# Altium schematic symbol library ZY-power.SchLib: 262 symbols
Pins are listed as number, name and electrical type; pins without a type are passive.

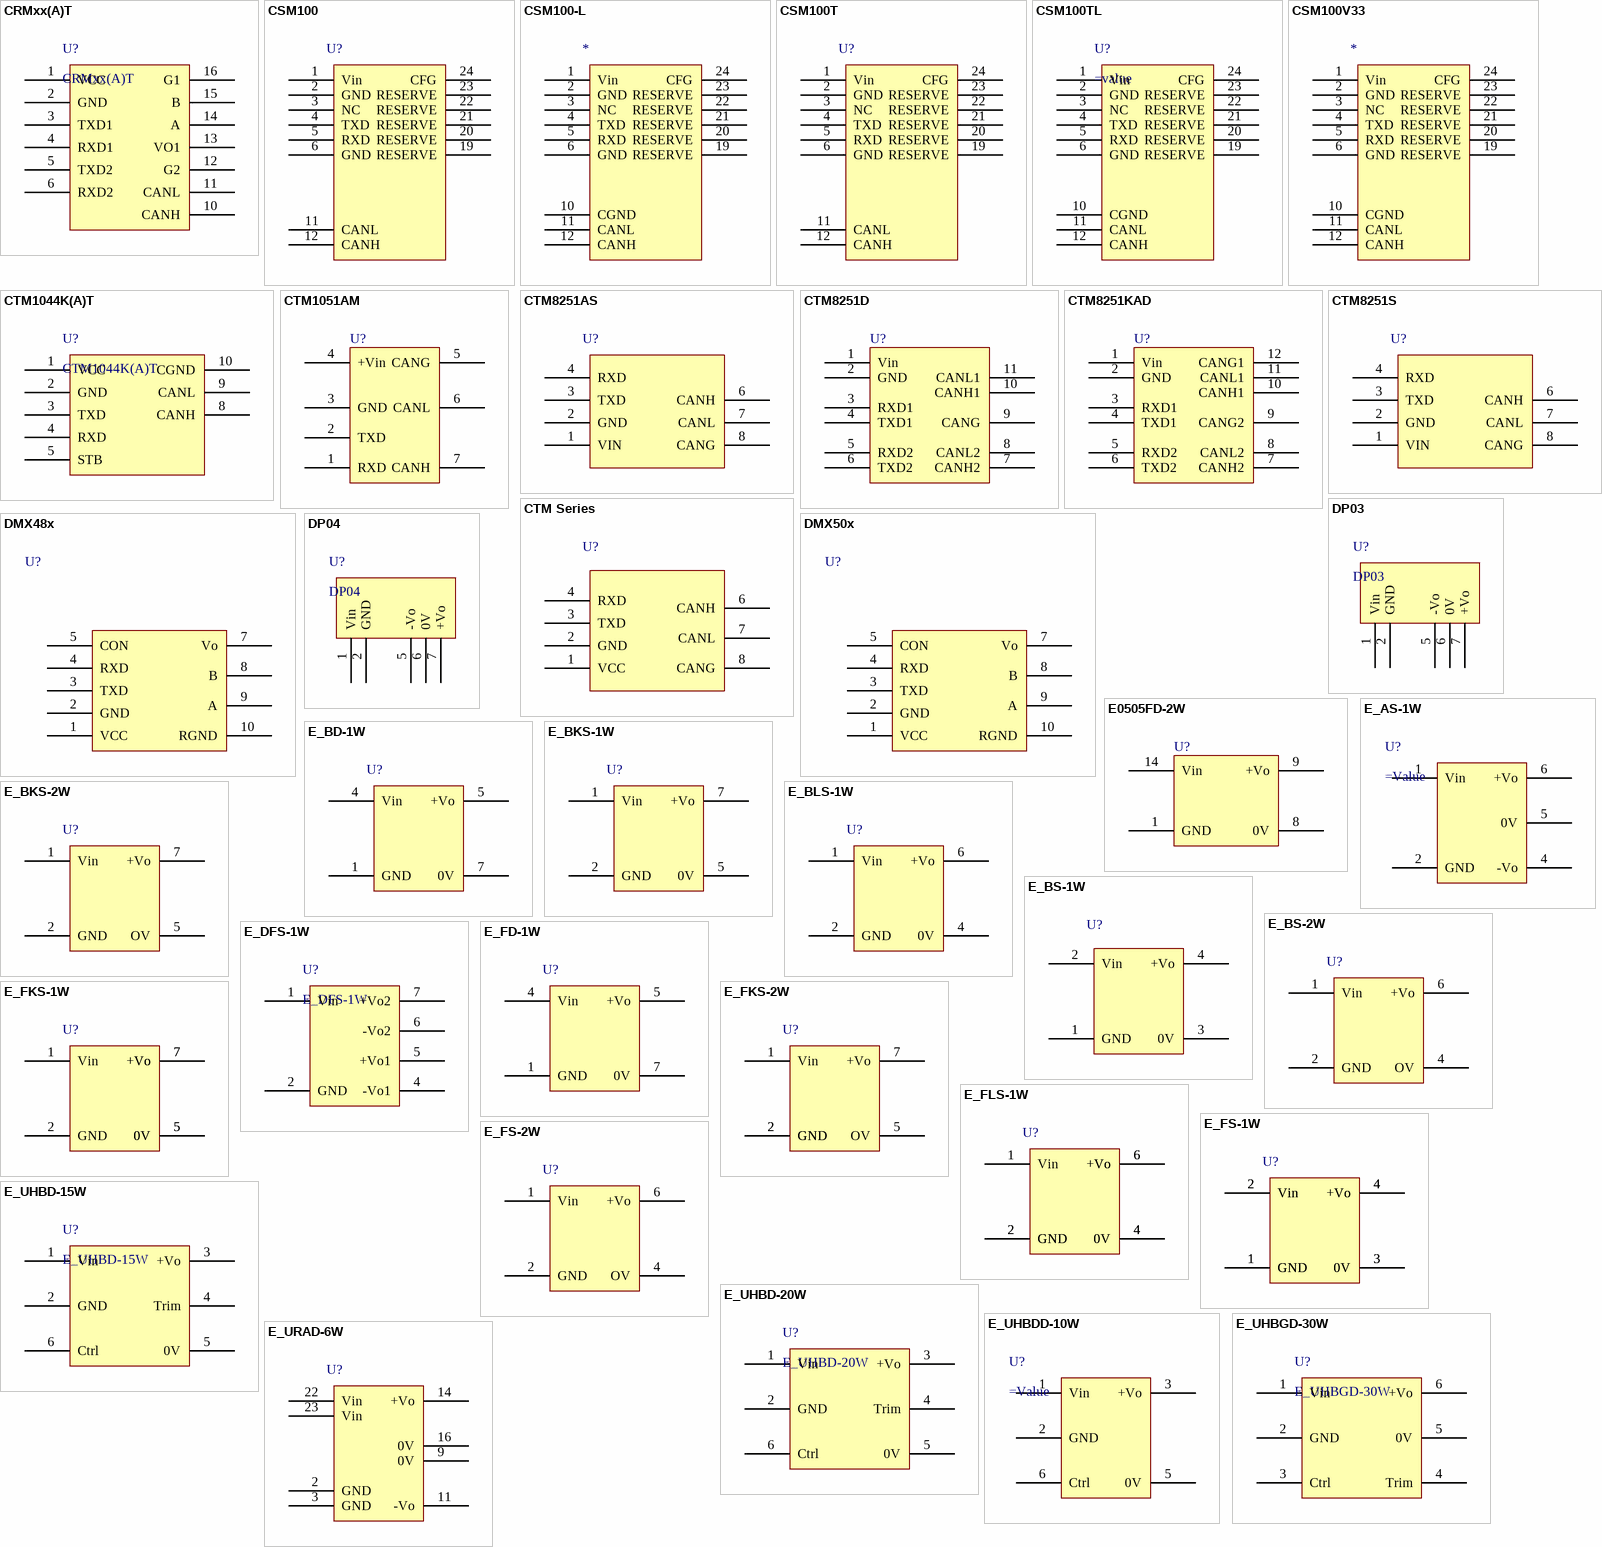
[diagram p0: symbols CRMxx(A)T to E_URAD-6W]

## CRMxx(A)T
designator U?
footprint CRMxx(A)T
pins: 1 VCC, 2 GND, 3 TXD1, 4 RXD1, 5 TXD2, 6 RXD2, 10 CANH, 11 CANL, 12 G2, 13 VO1, 14 A, 15 B, 16 G1

## CSM100
designator U?
footprint CSM100 (嵌入式CAN-bus接口芯片)
pins: 1 Vin, 2 GND, 3 NC, 4 TXD, 5 RXD, 6 GND, 11 CANL, 12 CANH, 19 RESERVE, 20 RESERVE, 21 RESERVE, 22 RESERVE, 23 RESERVE, 24 CFG

## CSM100-L
designator *
footprint CSM100-L
pins: 1 Vin, 2 GND, 3 NC, 4 TXD, 5 RXD, 6 GND, 10 CGND, 11 CANL, 12 CANH, 19 RESERVE, 20 RESERVE, 21 RESERVE, 22 RESERVE, 23 RESERVE, 24 CFG

## CSM100T
designator U?
footprint CSM100T (Footprint not found)
pins: 1 Vin, 2 GND, 3 NC, 4 TXD, 5 RXD, 6 GND, 11 CANL, 12 CANH, 19 RESERVE, 20 RESERVE, 21 RESERVE, 22 RESERVE, 23 RESERVE, 24 CFG

## CSM100TL
designator U?
CSM100TL
footprint CSM100TL
pins: 1 Vin, 2 GND, 3 NC, 4 TXD, 5 RXD, 6 GND, 10 CGND, 11 CANL, 12 CANH, 19 RESERVE, 20 RESERVE, 21 RESERVE, 22 RESERVE, 23 RESERVE, 24 CFG

## CSM100V33
designator *
footprint CSM100V33 (Footprint not found)
pins: 1 Vin, 2 GND, 3 NC, 4 TXD, 5 RXD, 6 GND, 10 CGND, 11 CANL, 12 CANH, 19 RESERVE, 20 RESERVE, 21 RESERVE, 22 RESERVE, 23 RESERVE, 24 CFG

## CTM1044K(A)T
designator U?
footprint CTM1044K(A)T
pins: 1 VCC, 2 GND, 3 TXD, 4 RXD, 5 STB, 8 CANH, 9 CANL, 10 CGND

## CTM1051AM
designator U?
pins: 1 RXD, 2 TXD, 3 GND, 4 +Vin, 5 CANG, 6 CANL, 7 CANH

## CTM8251AS
designator U?
CTM8251AS
footprint CTM8251AS
pins: 1 VIN, 2 GND, 3 TXD, 4 RXD, 6 CANH, 7 CANL, 8 CANG

## CTM8251D
designator U?
footprint CTM8251D
pins: 1 Vin, 2 GND, 3 RXD1, 4 TXD1, 5 RXD2, 6 TXD2, 7 CANH2, 8 CANL2, 9 CANG, 10 CANH1, 11 CANL1

## CTM8251KAD
designator U?
pins: 1 Vin, 2 GND, 3 RXD1, 4 TXD1, 5 RXD2, 6 TXD2, 7 CANH2, 8 CANL2, 9 CANG2, 10 CANH1, 11 CANL1, 12 CANG1

## CTM8251S
designator U?
CTM8251S
footprint CTM8251S
pins: 1 VIN, 2 GND, 3 TXD, 4 RXD, 6 CANH, 7 CANL, 8 CANG

## CTM Series
designator U?
footprint CTM Series (Footprint not found)
pins: 1 VCC, 2 GND, 3 TXD, 4 RXD, 6 CANH, 7 CANL, 8 CANG

## DMX48x
designator U?
footprint DMX48x
pins: 1 VCC, 2 GND, 3 TXD, 4 RXD, 5 CON, 7 Vo, 8 B, 9 A, 10 RGND
2 alternate drawings of the same symbol

## DMX50x
designator U?
footprint DMX50x
pins: 1 VCC, 2 GND, 3 TXD, 4 RXD, 5 CON, 7 Vo, 8 B, 9 A, 10 RGND
2 alternate drawings of the same symbol

## DP03
designator U?
footprint DP03
pins: 1 Vin, 2 GND, 5 -Vo, 6 0V, 7 +Vo

## DP04
designator U?
footprint DP04
pins: 1 Vin, 2 GND, 5 -Vo, 6 0V, 7 +Vo

## E0505FD-2W
designator U?
pins: 1 GND, 8 0V, 9 +Vo, 14 Vin

## E_AS-1W
designator U?
footprint E_AS-1W
pins: 1 Vin, 2 GND, 4 -Vo, 5 0V, 6 +Vo

## E_BD-1W
designator U?
footprint E_BD-1W
pins: 1 GND, 4 Vin, 5 +Vo, 7 0V

## E_BKS-1W
designator U?
footprint E_BKS-1W
pins: 1 Vin, 2 GND, 5 0V, 7 +Vo

## E_BKS-2W
designator U?
footprint E_BKS-2W
pins: 1 Vin, 2 GND, 5 OV, 7 +Vo

## E_BLS-1W
designator U?
footprint E_BLS-1W
pins: 1 Vin, 2 GND, 4 0V, 6 +Vo

## E_BS-1W
designator U?
footprint E_BS-1W
pins: 1 GND, 2 Vin, 3 0V, 4 +Vo

## E_BS-2W
designator U?
footprint E_BS-2W
pins: 1 Vin, 2 GND, 4 OV, 6 +Vo

## E_DFS-1W
designator U?
footprint E_DFS-1W
pins: 1 Vin, 2 GND, 4 -Vo1, 5 +Vo1, 6 -Vo2, 7 +Vo2

## E_FD-1W
designator U?
footprint E_FD-1W
pins: 1 GND, 4 Vin, 5 +Vo, 7 0V

## E_FKS-1W
designator U?
footprint E_FKS-1W
pins: 1 Vin, 2 GND, 5 0V, 5 0V, 7 +Vo, 7 +Vo

## E_FKS-2W
designator U?
footprint E_FKS-2W
pins: 1 Vin, 2 GND, 2 GND, 5 OV, 7 +Vo

## E_FLS-1W
designator U?
footprint E_FLS-1W
pins: 1 Vin, 2 GND, 2 GND, 4 0V, 4 0V, 6 +Vo, 6 +Vo

## E_FS-1W
designator U?
pins: 1 GND, 1 GND, 2 Vin, 2 Vin, 3 0V, 3 0V, 4 +Vo, 4 +Vo

## E_FS-2W
designator U?
footprint E_FS-2W
pins: 1 Vin, 2 GND, 4 OV, 6 +Vo

## E_UHBD-15W
designator U?
footprint E_UHBD-15W
pins: 1 Vin, 2 GND, 3 +Vo, 4 Trim, 5 0V, 6 Ctrl

## E_UHBD-20W
designator U?
footprint E_UHBD-20W
pins: 1 Vin, 2 GND, 3 +Vo, 4 Trim, 5 0V, 6 Ctrl

## E_UHBDD-10W
designator U?
footprint E_UHBDD-10W
pins: 1 Vin, 2 GND, 3 +Vo, 5 0V, 6 Ctrl

## E_UHBGD-30W
designator U?
footprint E_UHBGD-30W
pins: 1 Vin, 2 GND, 3 Ctrl, 4 Trim, 5 0V, 6 +Vo

## E_URAD-6W
designator U?
footprint E_URAD-6W
pins: 2 GND, 3 GND, 9 0V, 11 -Vo, 14 +Vo, 16 0V, 22 Vin, 23 Vin

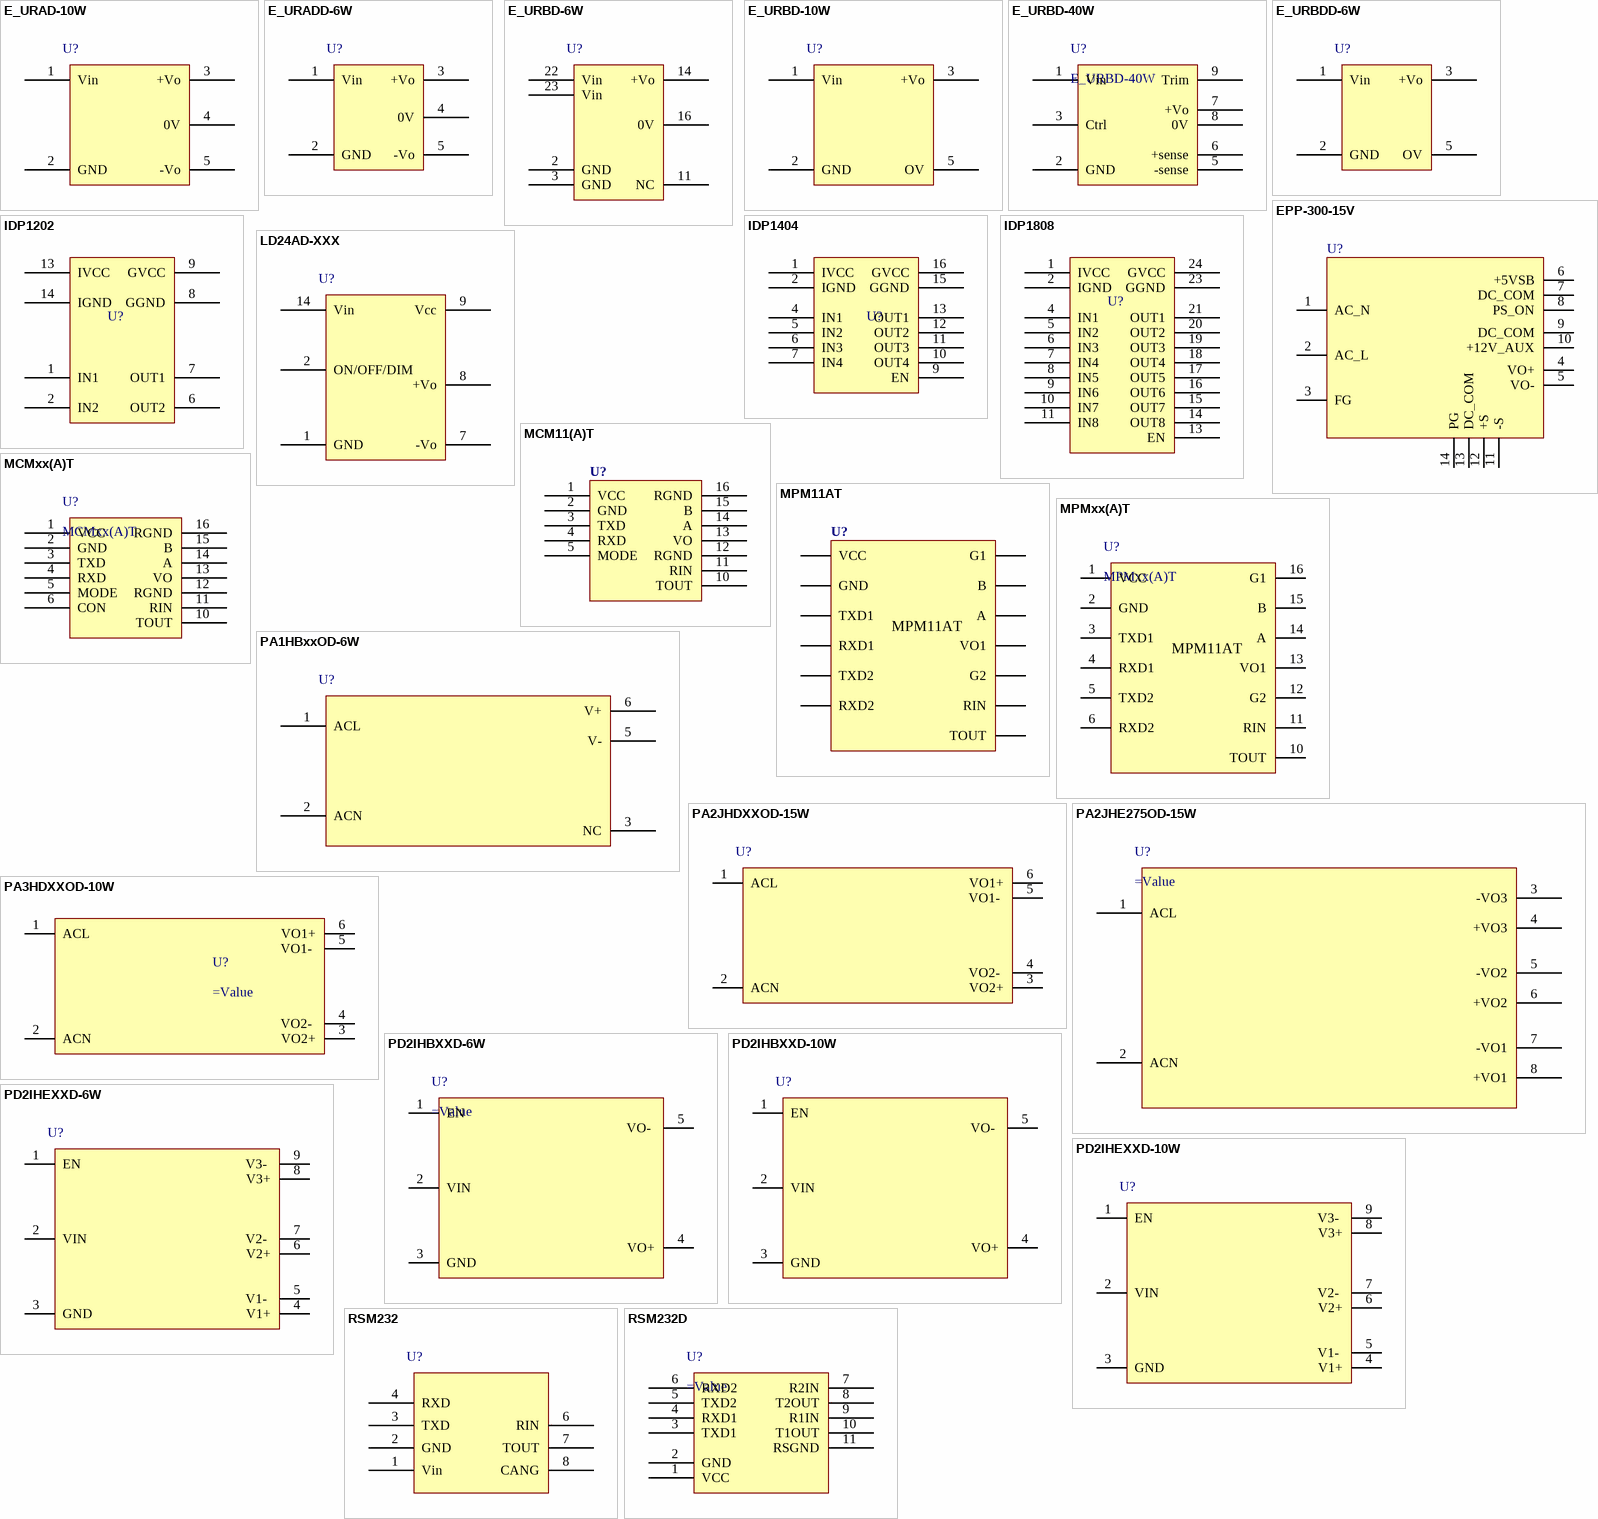
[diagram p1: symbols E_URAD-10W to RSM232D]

## E_URAD-10W
designator U?
footprint E_URAD-10W
pins: 1 Vin, 2 GND, 3 +Vo, 4 0V, 5 -Vo

## E_URADD-6W
designator U?
footprint E_URADD-6W
pins: 1 Vin, 2 GND, 3 +Vo, 4 0V, 5 -Vo

## E_URBD-6W
designator U?
footprint E_URBD-6W
pins: 2 GND, 3 GND, 11 NC, 14 +Vo, 16 0V, 22 Vin, 23 Vin

## E_URBD-10W
designator U?
footprint E_URBD-10W
pins: 1 Vin, 2 GND, 3 +Vo, 5 OV

## E_URBD-40W
designator U?
footprint E_URBD-40W
pins: 1 Vin, 2 GND, 3 Ctrl, 5 -sense, 6 +sense, 7 +Vo, 8 0V, 9 Trim

## E_URBDD-6W
designator U?
footprint E_URBDD-6W
pins: 1 Vin, 2 GND, 3 +Vo, 5 OV

## EPP-300-15V
designator U?
pins: 1 AC_N, 2 AC_L, 3 FG, 4 VO+, 5 VO-, 6 +5VSB, 7 DC_COM, 8 PS_ON, 9 DC_COM, 10 +12V_AUX, 11 -S, 12 +S, 13 DC_COM, 14 PG

## IDP1202
designator U?
footprint IDP1202 (20x10x8mm)
pins: 1 IN1, 2 IN2, 6 OUT2, 7 OUT1, 8 GGND, 9 GVCC, 13 IVCC, 14 IGND

## IDP1404
designator U?
footprint IDP1404
pins: 1 IVCC, 2 IGND, 4 IN1, 5 IN2, 6 IN3, 7 IN4, 9 EN, 10 OUT4, 11 OUT3, 12 OUT2, 13 OUT1, 15 GGND, 16 GVCC

## IDP1808
designator U?
footprint IDP1808 (32.32x14.41x6.7(9.65)mm)
pins: 1 IVCC, 2 IGND, 4 IN1, 5 IN2, 6 IN3, 7 IN4, 8 IN5, 9 IN6, 10 IN7, 11 IN8, 13 EN, 14 OUT8, 15 OUT7, 16 OUT6, 17 OUT5, 18 OUT4, 19 OUT3, 20 OUT2, 21 OUT1, 23 GGND, 24 GVCC

## LD24AD-XXX
designator U?
footprint LD24AD-XXX
pins: 1 GND, 2 ON/OFF/DIM, 7 -Vo, 8 +Vo, 9 Vcc, 14 Vin

## MCM11(A)T
designator U?
pins: 1 VCC, 2 GND, 3 TXD, 4 RXD, 5 MODE, 10 TOUT, 11 RIN, 12 RGND, 13 VO, 14 A, 15 B, 16 RGND

## MCMxx(A)T
designator U?
footprint MCMxx(A)T
pins: 1 VCC, 2 GND, 3 TXD, 4 RXD, 5 MODE, 6 CON, 10 TOUT, 11 RIN, 12 RGND, 13 VO, 14 A, 15 B, 16 RGND

## MPM11AT
designator U?
pins: 1 VCC, 2 GND, 3 TXD1, 4 RXD1, 5 TXD2, 6 RXD2, 10 TOUT, 11 RIN, 12 G2, 13 VO1, 14 A, 15 B, 16 G1

## MPMxx(A)T
designator U?
footprint MPMxx(A)T
pins: 1 VCC, 2 GND, 3 TXD1, 4 RXD1, 5 TXD2, 6 RXD2, 10 TOUT, 11 RIN, 12 G2, 13 VO1, 14 A, 15 B, 16 G1

## PA1HBxxOD-6W
designator U?
footprint PA1HBxxOD-6W
pins: 1 ACL, 2 ACN, 3 NC, 5 V-, 6 V+

## PA2JHDXXOD-15W
designator U?
footprint PA2JHDXXOD-15W
pins: 1 ACL, 2 ACN, 3 VO2+, 4 VO2- , 5 VO1- , 6 VO1+

## PA2JHE275OD-15W
designator U?
footprint PA2JHE275OD-15W
pins: 1 ACL, 2 ACN, 3 -VO3, 4 +VO3, 5 -VO2, 6 +VO2, 7 -VO1, 8 +VO1

## PA3HDXXOD-10W
designator U?
footprint PA3HDXXOD-10W
pins: 1 ACL, 2 ACN, 3 VO2+, 4 VO2- , 5 VO1- , 6 VO1+

## PD2IHBXXD-6W
designator U?
footprint PD2IHBXXD-6W
pins: 1 EN, 2 VIN, 3 GND, 4 VO+, 5 VO- 

## PD2IHBXXD-10W
designator U?
footprint PD2IHBXXD-10W
pins: 1 EN, 2 VIN, 3 GND, 4 VO+, 5 VO- 

## PD2IHEXXD-6W
designator U?
footprint PD2IHEXXD-6W
pins: 1 EN, 2 VIN, 3 GND, 4 V1+, 5 V1- , 6 V2+, 7 V2- , 8 V3+, 9 V3- 

## PD2IHEXXD-10W
designator U?
footprint PD2IHEXXD-10W
pins: 1 EN, 2 VIN, 3 GND, 4 V1+, 5 V1- , 6 V2+, 7 V2- , 8 V3+, 9 V3- 

## RSM232
designator U?
footprint RSM232 (Footprint not found)
pins: 1 Vin, 2 GND, 3 TXD, 4 RXD, 6 RIN, 7 TOUT, 8 CANG

## RSM232D
designator U?
footprint RSM232D
pins: 1 VCC, 2 GND, 3 TXD1, 4 RXD1, 5 TXD2, 6 RXD2, 7 R2IN, 8 T2OUT, 9 R1IN, 10 T1OUT, 11 RSGND

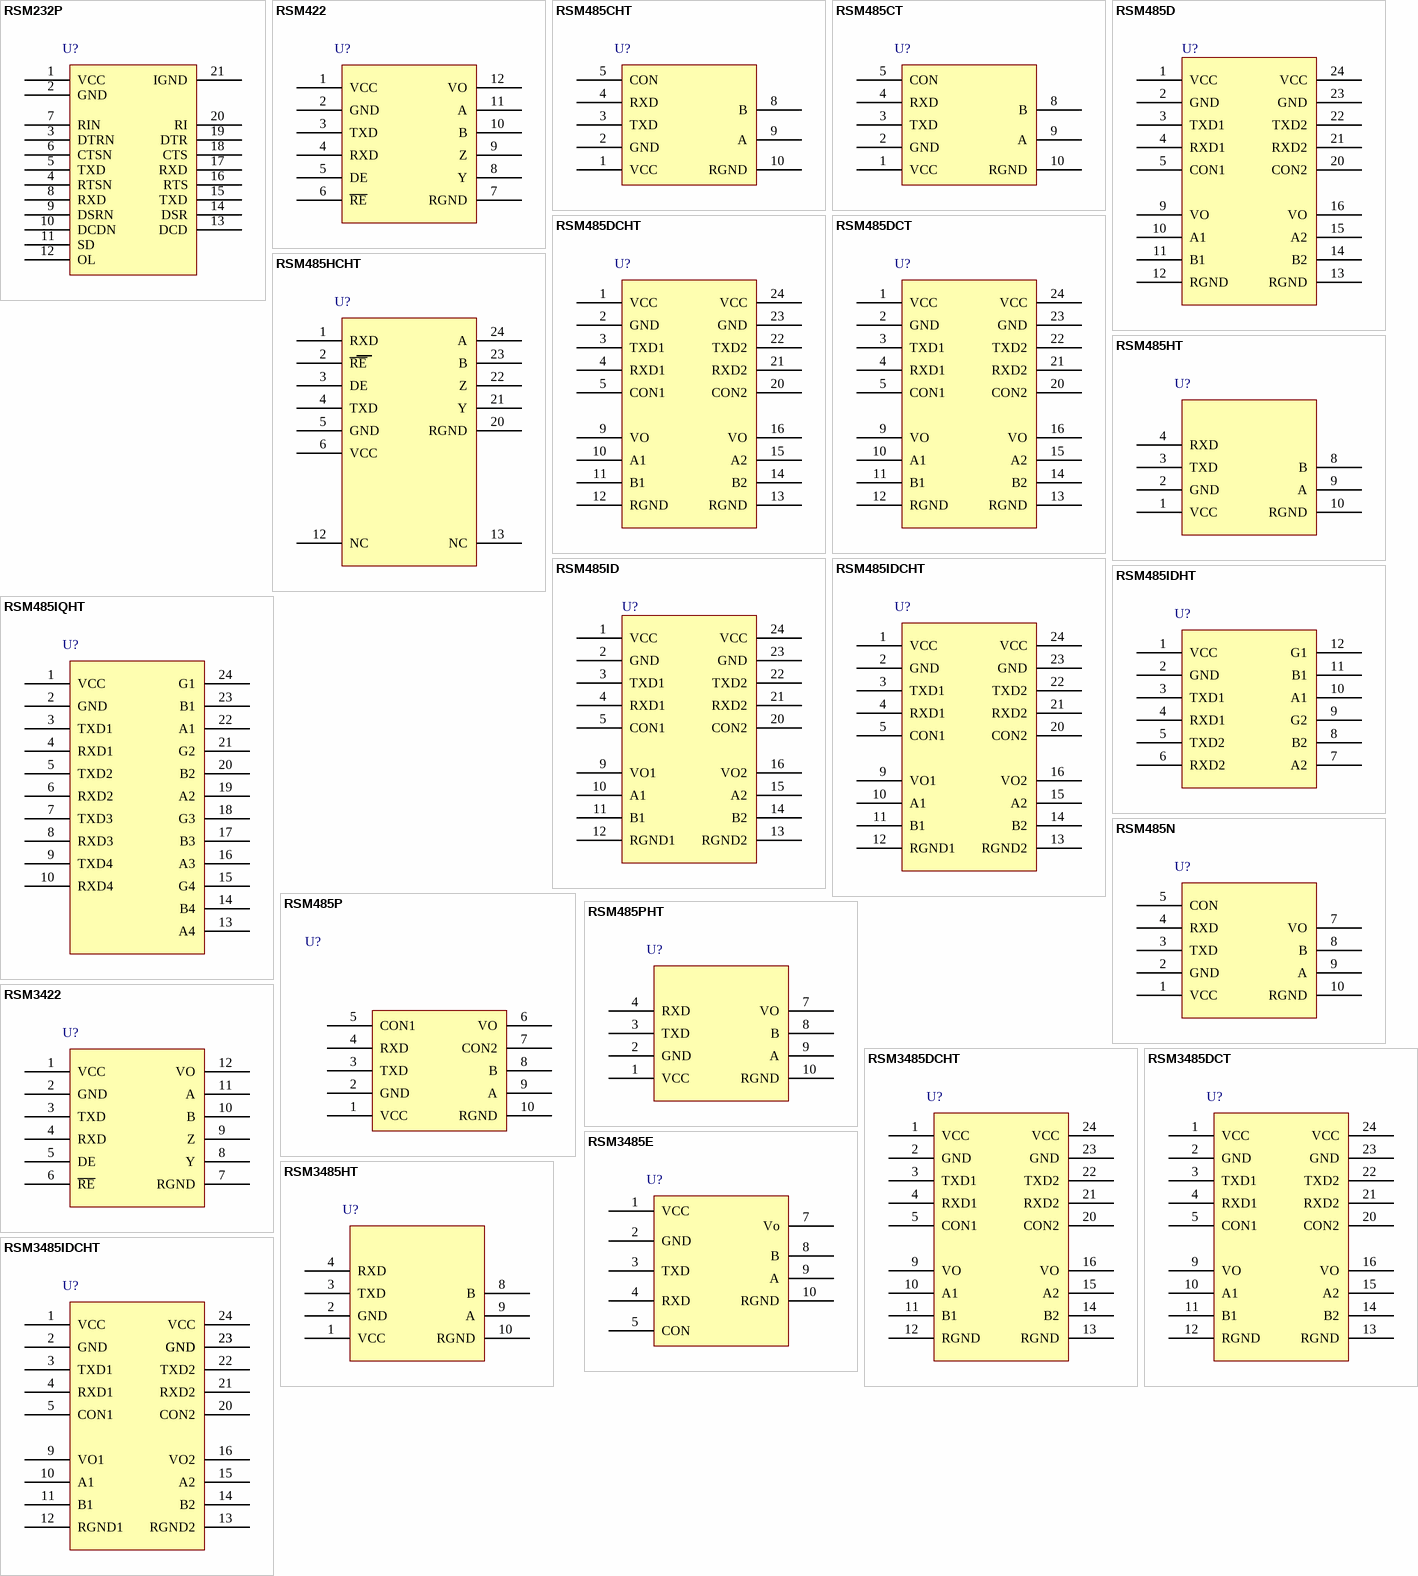
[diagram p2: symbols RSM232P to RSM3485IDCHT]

## RSM232P
designator U?
footprint RSM232P (Footprint not found)
pins: 1 VCC, 2 GND, 3 DTRN, 4 RTSN, 5 TXD, 6 CTSN, 7 RIN, 8 RXD, 9 DSRN, 10 DCDN, 11 SD, 12 OL, 13 DCD, 14 DSR, 15 TXD, 16 RTS, 17 RXD, 18 CTS, 19 DTR, 20 RI, 21 IGND

## RSM422
designator U?
RSM422
footprint RSM422
pins: 1 VCC, 2 GND, 3 TXD, 4 RXD, 5 DE, 6 ~{RE}, 7 RGND, 8 Y, 9 Z, 10 B, 11 A, 12 VO

## RSM485CHT
designator U?
footprint RSM485CHT (Footprint not found)
pins: 1 VCC, 2 GND, 3 TXD, 4 RXD, 5 CON, 8 B, 9 A, 10 RGND

## RSM485CT
designator U?
footprint RSM485CT (Footprint not found)
pins: 1 VCC, 2 GND, 3 TXD, 4 RXD, 5 CON, 8 B, 9 A, 10 RGND

## RSM485D
designator U?
footprint RSM485D
pins: 1 VCC, 2 GND, 3 TXD1, 4 RXD1, 5 CON1, 9 VO, 10 A1, 11 B1, 12 RGND, 13 RGND, 14 B2, 15 A2, 16 VO, 20 CON2, 21 RXD2, 22 TXD2, 23 GND, 24 VCC
2 alternate drawings of the same symbol

## RSM485DCHT
designator U?
RSM485DCHT
footprint RSM485DCHT
pins: 1 VCC, 2 GND, 3 TXD1, 4 RXD1, 5 CON1, 9 VO, 10 A1, 11 B1, 12 RGND, 13 RGND, 14 B2, 15 A2, 16 VO, 20 CON2, 21 RXD2, 22 TXD2, 23 GND, 24 VCC

## RSM485DCT
designator U?
RSM485DCT
footprint RSM485DCT
pins: 1 VCC, 2 GND, 3 TXD1, 4 RXD1, 5 CON1, 9 VO, 10 A1, 11 B1, 12 RGND, 13 RGND, 14 B2, 15 A2, 16 VO, 20 CON2, 21 RXD2, 22 TXD2, 23 GND, 24 VCC

## RSM485HCHT
designator U?
RSM485HCHT
footprint RSM485HCHT
pins: 1 RXD, 2 ~{RE}, 3 DE, 4 TXD, 5 GND, 6 VCC, 12 NC, 13 NC, 20 RGND, 21 Y, 22 Z, 23 B, 24 A

## RSM485HT
designator U?
RSM485HT
footprint RSM485HT
pins: 1 VCC, 2 GND, 3 TXD, 4 RXD, 8 B, 9 A, 10 RGND

## RSM485ID
designator U?
footprint RSM485D
pins: 1 VCC, 2 GND, 3 TXD1, 4 RXD1, 5 CON1, 9 VO1, 10 A1, 11 B1, 12 RGND1, 13 RGND2, 14 B2, 15 A2, 16 VO2, 20 CON2, 21 RXD2, 22 TXD2, 23 GND, 24 VCC
2 alternate drawings of the same symbol

## RSM485IDCHT
designator U?
RSM485IDCHT
footprint RSM485IDCHT
pins: 1 VCC, 2 GND, 3 TXD1, 4 RXD1, 5 CON1, 9 VO1, 10 A1, 11 B1, 12 RGND1, 13 RGND2, 14 B2, 15 A2, 16 VO2, 20 CON2, 21 RXD2, 22 TXD2, 23 GND, 24 VCC

## RSM485IDHT
designator U?
RSM485IDHT
footprint RSM485IDHT
pins: 1 VCC, 2 GND, 3 TXD1, 4 RXD1, 5 TXD2, 6 RXD2, 7 A2, 8 B2, 9 G2, 10 A1, 11 B1, 12 G1

## RSM485IQHT
designator U?
RSM485IQHT
footprint RSM485IQHT
pins: 1 VCC, 2 GND, 3 TXD1, 4 RXD1, 5 TXD2, 6 RXD2, 7 TXD3, 8 RXD3, 9 TXD4, 10 RXD4, 13 A4, 14 B4, 15 G4, 16 A3, 17 B3, 18 G3, 19 A2, 20 B2, 21 G2, 22 A1, 23 B1, 24 G1

## RSM485N
designator U?
RSM485N
footprint RSM485N
pins: 1 VCC, 2 GND, 3 TXD, 4 RXD, 5 CON, 7 VO, 8 B, 9 A, 10 RGND

## RSM485P
designator U?
RSM485P
footprint RSM485P
pins: 1 VCC, 2 GND, 3 TXD, 4 RXD, 5 CON1, 6 VO, 7 CON2, 8 B, 9 A, 10 RGND
2 alternate drawings of the same symbol

## RSM485PHT
designator U?
RSM485PHT
footprint RSM485PHT
pins: 1 VCC, 2 GND, 3 TXD, 4 RXD, 7 VO, 8 B, 9 A, 10 RGND

## RSM3422
designator U?
RSM3422
footprint RSM3422
pins: 1 VCC, 2 GND, 3 TXD, 4 RXD, 5 DE, 6 ~{RE}, 7 RGND, 8 Y, 9 Z, 10 B, 11 A, 12 VO

## RSM3485DCHT
designator U?
RSM3485DCHT
footprint RSM3485DCHT
pins: 1 VCC, 2 GND, 3 TXD1, 4 RXD1, 5 CON1, 9 VO, 10 A1, 11 B1, 12 RGND, 13 RGND, 14 B2, 15 A2, 16 VO, 20 CON2, 21 RXD2, 22 TXD2, 23 GND, 24 VCC

## RSM3485DCT
designator U?
RSM3485DCT
footprint RSM3485DCT
pins: 1 VCC, 2 GND, 3 TXD1, 4 RXD1, 5 CON1, 9 VO, 10 A1, 11 B1, 12 RGND, 13 RGND, 14 B2, 15 A2, 16 VO, 20 CON2, 21 RXD2, 22 TXD2, 23 GND, 24 VCC

## RSM3485E
designator U?
pins: 1 VCC, 2 GND, 3 TXD, 4 RXD, 5 CON, 7 Vo, 8 B, 9 A, 10 RGND

## RSM3485HT
designator U?
RSM3485HT
footprint RSM3485HT
pins: 1 VCC, 2 GND, 3 TXD, 4 RXD, 8 B, 9 A, 10 RGND

## RSM3485IDCHT
designator U?
RSM3485IDCHT
footprint RSM3485IDCHT
pins: 1 VCC, 2 GND, 3 TXD1, 4 RXD1, 5 CON1, 9 VO1, 10 A1, 11 B1, 12 RGND1, 13 RGND2, 14 B2, 15 A2, 16 VO2, 20 CON2, 21 RXD2, 22 TXD2, 23 GND, 23 GND, 24 VCC

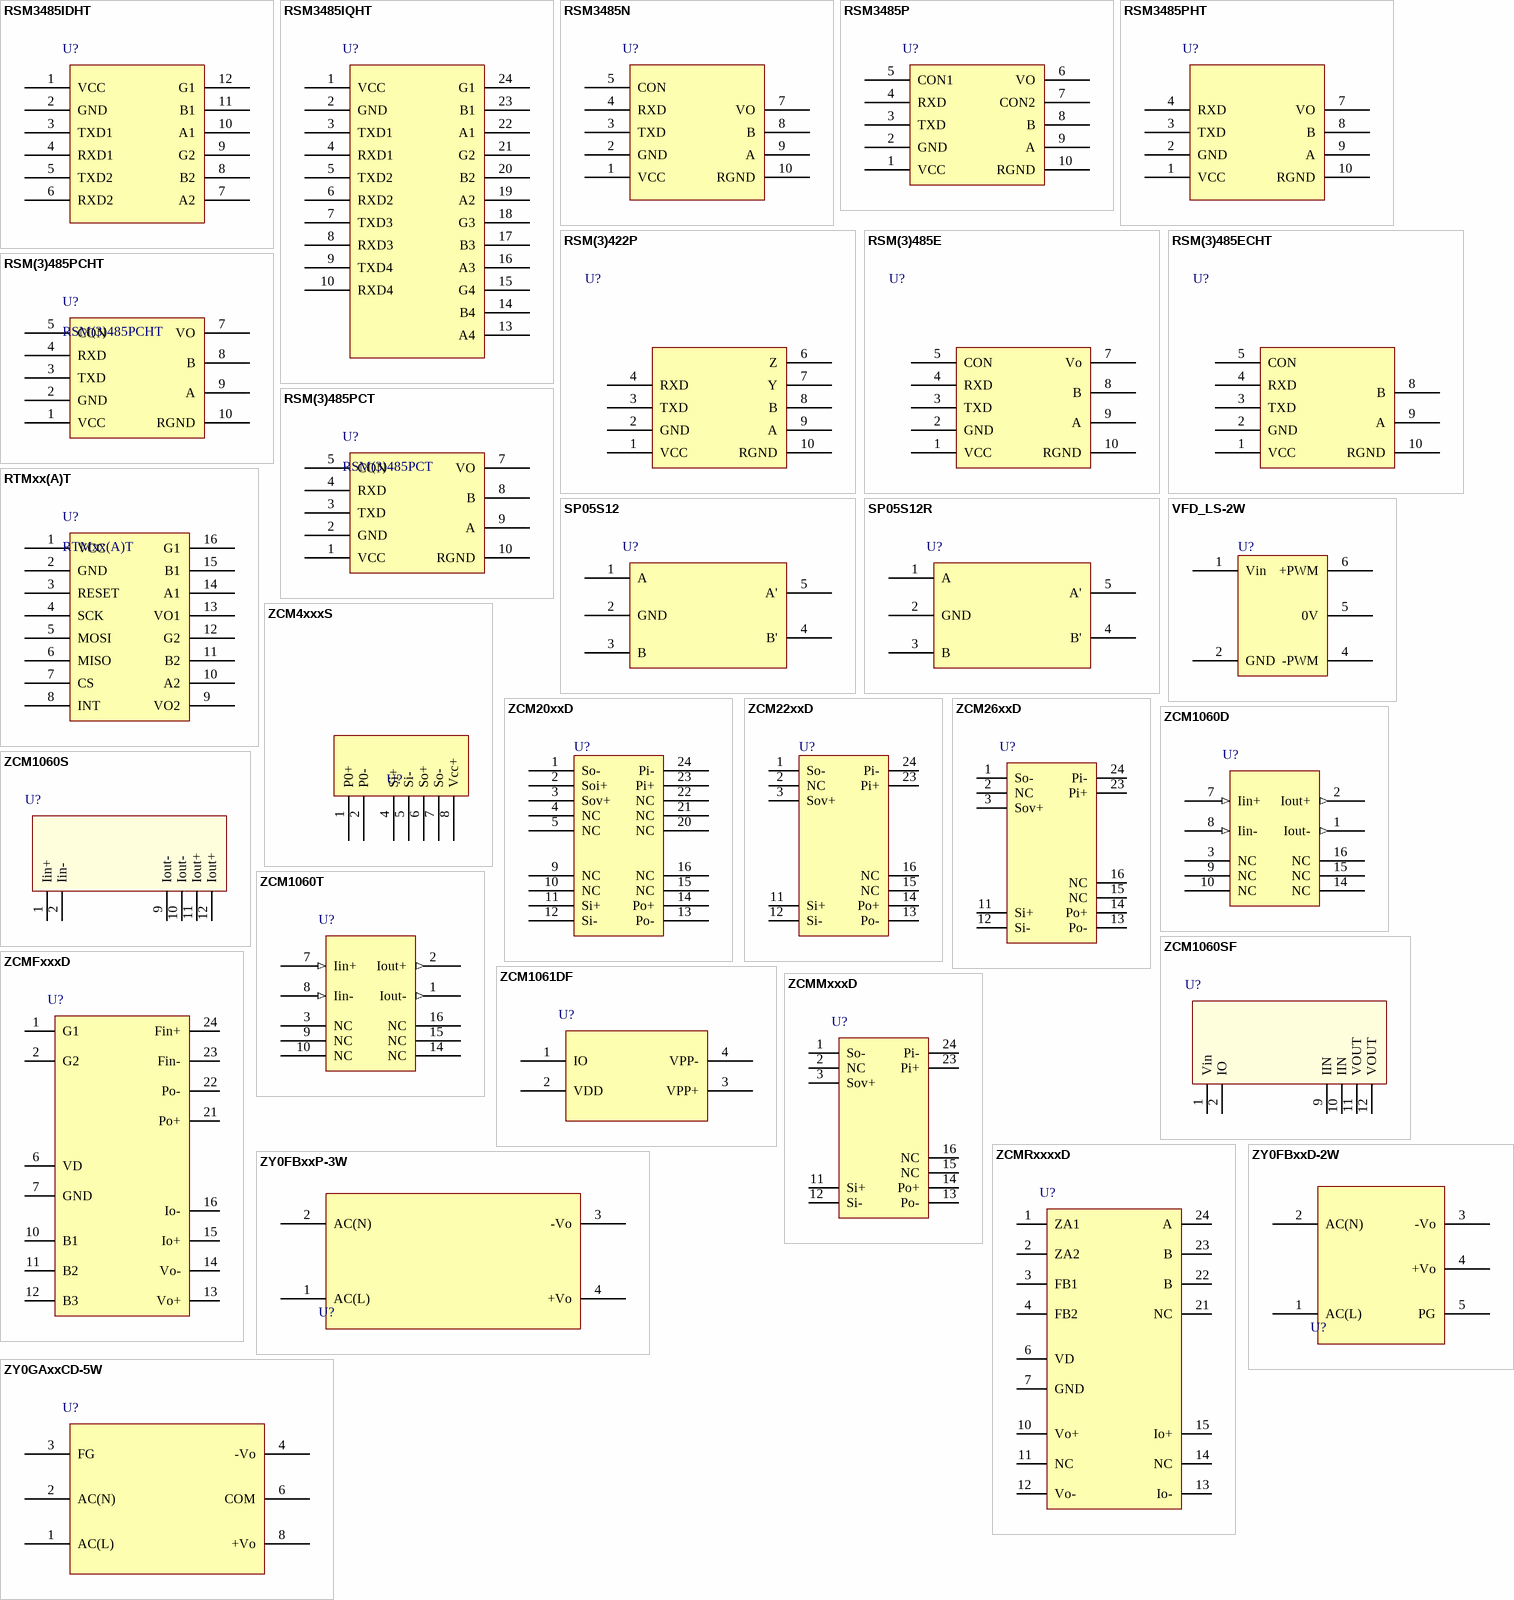
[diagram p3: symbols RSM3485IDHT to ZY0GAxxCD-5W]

## RSM3485IDHT
designator U?
RSM3485IDHT
footprint RSM3485IDHT
pins: 1 VCC, 2 GND, 3 TXD1, 4 RXD1, 5 TXD2, 6 RXD2, 7 A2, 8 B2, 9 G2, 10 A1, 11 B1, 12 G1

## RSM3485IQHT
designator U?
RSM3485IQHT
footprint RSM3485IQHT
pins: 1 VCC, 2 GND, 3 TXD1, 4 RXD1, 5 TXD2, 6 RXD2, 7 TXD3, 8 RXD3, 9 TXD4, 10 RXD4, 13 A4, 14 B4, 15 G4, 16 A3, 17 B3, 18 G3, 19 A2, 20 B2, 21 G2, 22 A1, 23 B1, 24 G1

## RSM3485N
designator U?
RSM3485N
footprint RSM3485N
pins: 1 VCC, 2 GND, 3 TXD, 4 RXD, 5 CON, 7 VO, 8 B, 9 A, 10 RGND

## RSM3485P
designator U?
RSM3485P
footprint RSM3485P
pins: 1 VCC, 2 GND, 3 TXD, 4 RXD, 5 CON1, 6 VO, 7 CON2, 8 B, 9 A, 10 RGND

## RSM3485PHT
designator U?
RSM3485PHT
footprint RSM3485PHT
pins: 1 VCC, 2 GND, 3 TXD, 4 RXD, 7 VO, 8 B, 9 A, 10 RGND

## RSM(3)422P
designator U?
footprint RSM(3)422P (Footprint not found)
pins: 1 VCC, 2 GND, 3 TXD, 4 RXD, 6 Z, 7 Y, 8 B, 9 A, 10 RGND
2 alternate drawings of the same symbol

## RSM(3)485E
designator U?
footprint RSM(3)485E
pins: 1 VCC, 2 GND, 3 TXD, 4 RXD, 5 CON, 7 Vo, 8 B, 9 A, 10 RGND
2 alternate drawings of the same symbol

## RSM(3)485ECHT
designator U?
footprint RSM(3)485ECHT
pins: 1 VCC, 2 GND, 3 TXD, 4 RXD, 5 CON, 8 B, 9 A, 10 RGND
2 alternate drawings of the same symbol

## RSM(3)485PCHT
designator U?
footprint RSM(3)485PCHT
pins: 1 VCC, 2 GND, 3 TXD, 4 RXD, 5 CON, 7 VO, 8 B, 9 A, 10 RGND

## RSM(3)485PCT
designator U?
footprint RSM(3)485PCT
pins: 1 VCC, 2 GND, 3 TXD, 4 RXD, 5 CON, 7 VO, 8 B, 9 A, 10 RGND

## RTMxx(A)T
designator U?
footprint RTMxx(A)T
pins: 1 VCC, 2 GND, 3 RESET, 4 SCK, 5 MOSI, 6 MISO, 7 CS, 8 INT, 9 VO2, 10 A2, 11 B2, 12 G2, 13 VO1, 14 A1, 15 B1, 16 G1

## SP05S12
designator U?
SP05S12
footprint SP05S12
pins: 1 A, 2 GND, 3 B, 4 B', 5 A'

## SP05S12R
designator U?
SP05S12R
footprint SP05S12R
pins: 1 A, 2 GND, 3 B, 4 B', 5 A'

## VFD_LS-2W
designator U?
pins: 1 Vin, 2 GND, 4 -PWM, 5 0V, 6 +PWM

## ZCM4xxxS
designator U?
footprint ZCM4xxxS
pins: 1 P0+, 2 P0-, 4 Si+, 5 Si-, 6 So+, 7 So-, 8 Vcc+

## ZCM20xxD
designator U?
footprint ZCM20xxD (Footprint not found)
pins: 1 So-, 2 Soi+, 3 Sov+, 4 NC, 5 NC, 9 NC, 10 NC, 11 Si+, 12 Si-, 13 Po-, 14 Po+, 15 NC, 16 NC, 20 NC, 21 NC, 22 NC, 23 Pi+, 24 Pi-

## ZCM22xxD
designator U?
footprint ZCM22xxD (Footprint not found)
pins: 1 So-, 2 NC, 3 Sov+, 11 Si+, 12 Si-, 13 Po-, 14 Po+, 15 NC, 16 NC, 23 Pi+, 24 Pi-

## ZCM26xxD
designator U?
footprint ZCM26xxD
pins: 1 So-, 2 NC, 3 Sov+, 11 Si+, 12 Si-, 13 Po-, 14 Po+, 15 NC, 16 NC, 23 Pi+, 24 Pi-

## ZCM1060D
designator U?
footprint ZCM1060D
pins: 1 Iout- (out), 2 Iout+ (out), 3 NC, 7 Iin+ (in), 8 Iin- (in), 9 NC, 10 NC, 14 NC, 15 NC, 16 NC

## ZCM1060S
designator U?
footprint ZCM1060S
pins: 1 Iin+, 2 Iin-, 9 Iout-, 10 Iout-, 11 Iout+, 12 Iout+

## ZCM1060SF
designator U?
footprint ZCM1060SF
pins: 1 Vin, 2 IO, 9 IIN, 10 IIN, 11 VOUT, 12 VOUT

## ZCM1060T
designator U?
footprint ZCM1060T
pins: 1 Iout- (out), 2 Iout+ (out), 3 NC, 7 Iin+ (in), 8 Iin- (in), 9 NC, 10 NC, 14 NC, 15 NC, 16 NC

## ZCM1061DF
designator U?
footprint ZCM1061DF
pins: 1 IO, 2 VDD, 3 VPP+, 4 VPP-

## ZCMFxxxD
designator U?
footprint ZCMFxxxD
pins: 1 G1, 2 G2, 6 VD, 7 GND, 10 B1, 11 B2, 12 B3, 13 Vo+, 14 Vo-, 15 Io+, 16 Io-, 21 Po+, 22 Po-, 23 Fin-, 24 Fin+

## ZCMMxxxD
designator U?
footprint ZCMMxxxD (Footprint not found)
pins: 1 So-, 2 NC, 3 Sov+, 11 Si+, 12 Si-, 13 Po-, 14 Po+, 15 NC, 16 NC, 23 Pi+, 24 Pi-

## ZCMRxxxxD
designator U?
footprint ZCMRxxxxD
pins: 1 ZA1, 2 ZA2, 3 FB1, 4 FB2, 6 VD, 7 GND, 10 Vo+, 11 NC, 12 Vo-, 13 Io-, 14 NC, 15 Io+, 21 NC, 22 B, 23 B, 24 A

## ZY0FBxxD-2W
designator U?
ZY0FBxxD-2W
footprint ZY0FBxxD-2W
pins: 1 AC(L), 2 AC(N), 3 -Vo, 4 +Vo, 5 PG

## ZY0FBxxP-3W
designator U?
footprint ZY0FBxxP-3W (Footprint not found)
pins: 1 AC(L), 2 AC(N), 3 -Vo, 4 +Vo

## ZY0GAxxCD-5W
designator U?
footprint ZY0GAxxCD-5W (Footprint not found)
pins: 1 AC(L), 2 AC(N), 3 FG, 4 -Vo, 6 COM, 8 +Vo

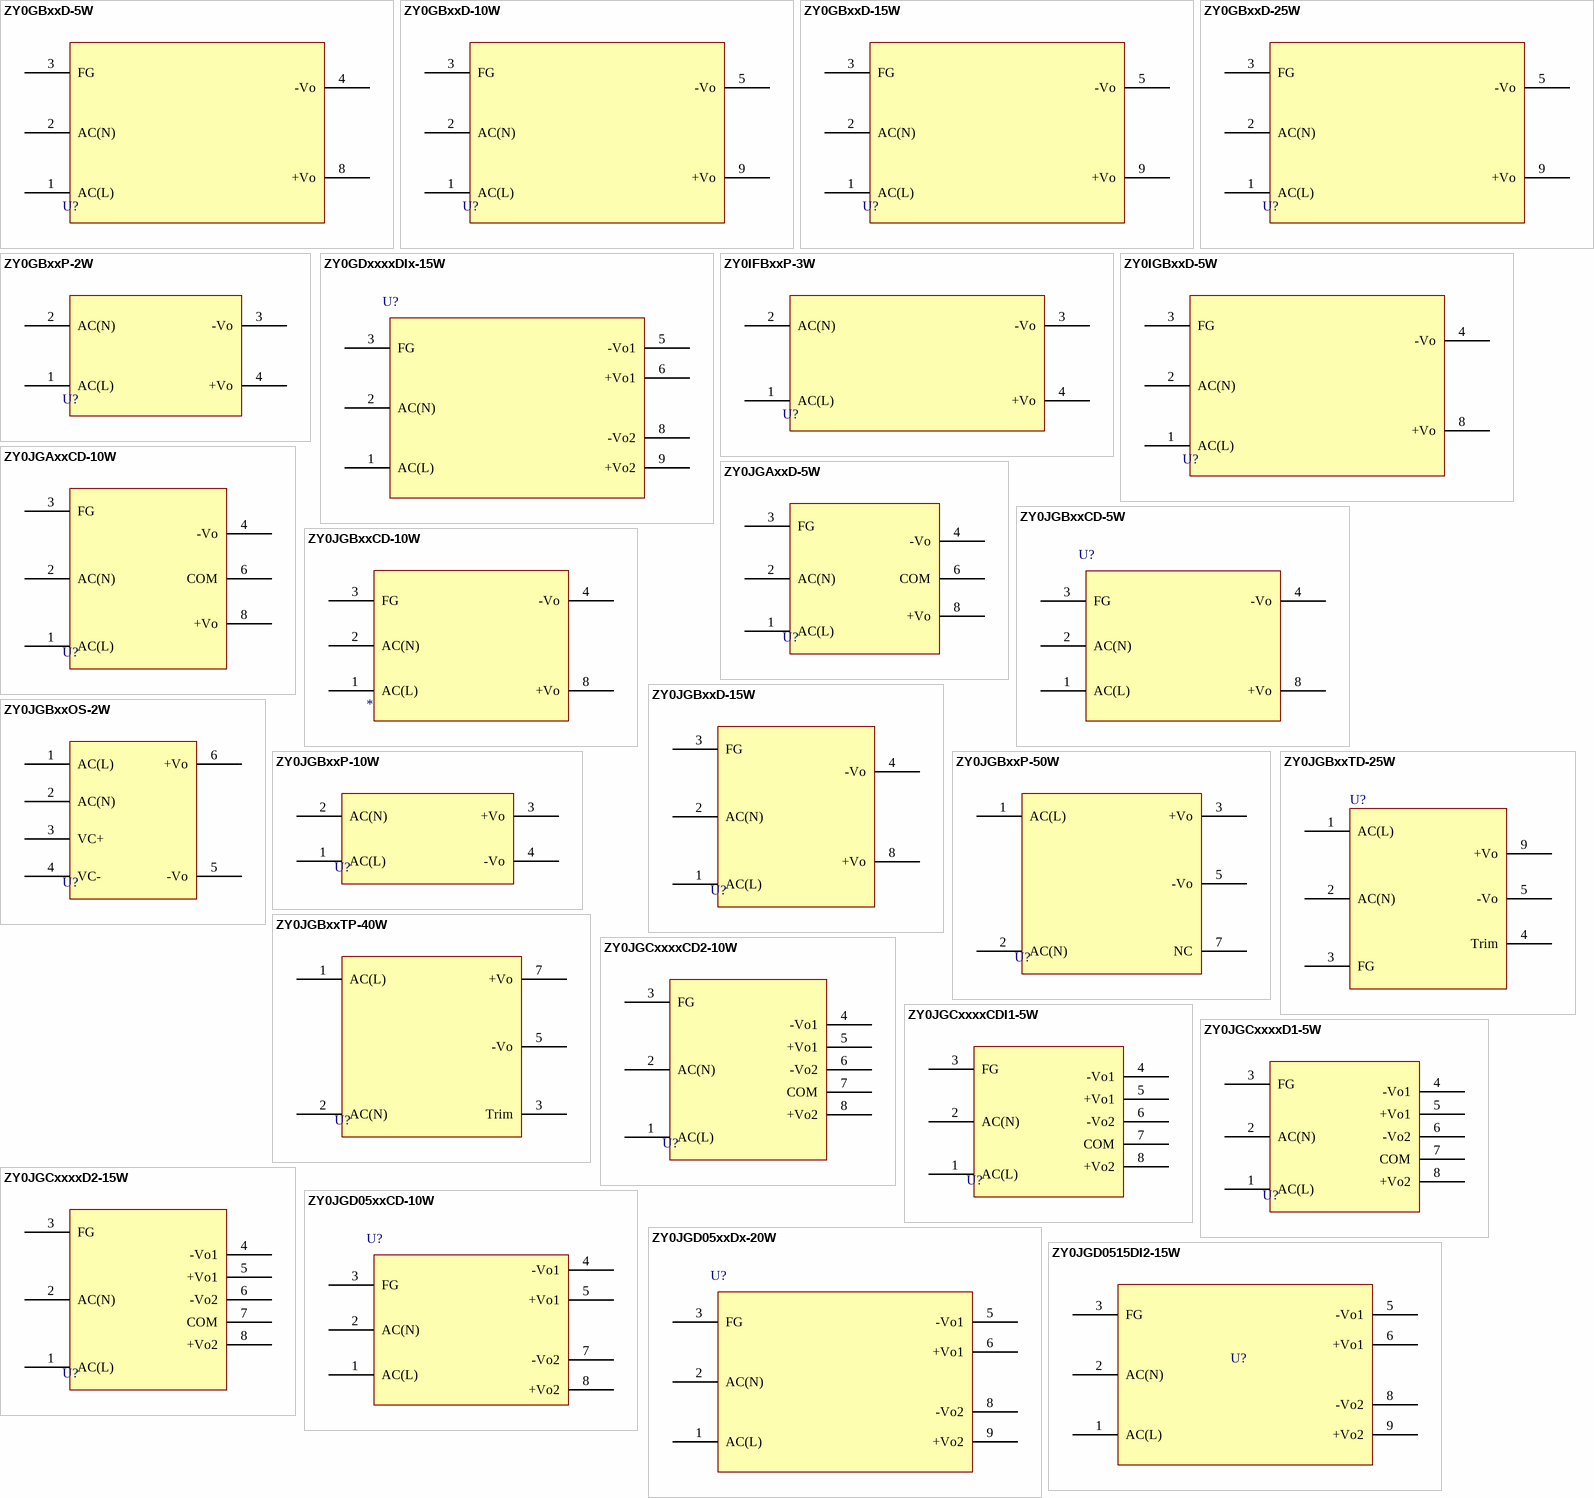
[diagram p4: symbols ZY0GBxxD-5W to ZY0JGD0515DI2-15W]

## ZY0GBxxD-5W
designator U?
footprint ZY0GBxxD-5W (Footprint not found)
pins: 1 AC(L), 2 AC(N), 3 FG, 4 -Vo, 8 +Vo

## ZY0GBxxD-10W
designator U?
footprint ZY0GBxxD-10W (Footprint not found)
pins: 1 AC(L), 2 AC(N), 3 FG, 5 -Vo, 9 +Vo

## ZY0GBxxD-15W
designator U?
footprint ZY0GBxxD-15W (Footprint not found)
pins: 1 AC(L), 2 AC(N), 3 FG, 5 -Vo, 9 +Vo

## ZY0GBxxD-25W
designator U?
footprint ZY0GBxxD-25W
pins: 1 AC(L), 2 AC(N), 3 FG, 5 -Vo, 9 +Vo

## ZY0GBxxP-2W
designator U?
ZY0GBxxP-2W
footprint ZY0GBxxP-2W
pins: 1 AC(L), 2 AC(N), 3 -Vo, 4 +Vo

## ZY0GDxxxxDIx-15W
designator U?
footprint ZY0GDxxxxDIx-15W (Footprint not found)
pins: 1 AC(L), 2 AC(N), 3 FG, 5 -Vo1, 6 +Vo1, 8 -Vo2, 9 +Vo2

## ZY0IFBxxP-3W
designator U?
footprint ZY0IFBxxP-3W
pins: 1 AC(L), 2 AC(N), 3 -Vo, 4 +Vo

## ZY0IGBxxD-5W
designator U?
footprint ZY0IGBxxD-5W (120426 修改 by kong)
pins: 1 AC(L), 2 AC(N), 3 FG, 4 -Vo, 8 +Vo

## ZY0JGAxxCD-10W
designator U?
ZY0JGAxxCD-10W
footprint ZY0JGAxxCD-10W
pins: 1 AC(L), 2 AC(N), 3 FG, 4 -Vo, 6 COM, 8 +Vo

## ZY0JGAxxD-5W
designator U?
ZY0JGAxxD-5W
footprint ZY0JGAxxD-5W
pins: 1 AC(L), 2 AC(N), 3 FG, 4 -Vo, 6 COM, 8 +Vo

## ZY0JGBxxCD-5W
designator U?
footprint ZY0JGBxxCD-5W (Footprint not found)
pins: 1 AC(L), 2 AC(N), 3 FG, 4 -Vo, 8 +Vo

## ZY0JGBxxCD-10W
designator *
footprint ZY0JGBxxCD-10W
pins: 1 AC(L), 2 AC(N), 3 FG, 4 -Vo, 8 +Vo

## ZY0JGBxxD-15W
designator U?
ZY0JGBxxD-15W
footprint ZY0JGBxxD-15W
pins: 1 AC(L), 2 AC(N), 3 FG, 4 -Vo, 8 +Vo

## ZY0JGBxxOS-2W
designator U?
footprint ZY0JGBxxOS-2W
pins: 1 AC(L), 2 AC(N), 3 VC+, 4 VC-, 5 -Vo, 6 +Vo

## ZY0JGBxxP-10W
designator U?
ZY0JGBxxP-10W
footprint ZY0JGBxxP-10W
pins: 1 AC(L), 2 AC(N), 3 +Vo, 4 -Vo

## ZY0JGBxxP-50W
designator U?
ZY0JGBxxP-50W
footprint ZY0JGBxxP-50W
pins: 1 AC(L), 2 AC(N), 3 +Vo, 5 -Vo, 7 NC

## ZY0JGBxxTD-25W
designator U?
ZY0JGB24TD-25W
pins: 1 AC(L), 2 AC(N), 3 FG, 4 Trim, 5 -Vo, 9 +Vo

## ZY0JGBxxTP-40W
designator U?
ZY0JGBxxTP-40W
footprint ZY0JGBxxTP-40W
pins: 1 AC(L), 2 AC(N), 3 Trim, 5 -Vo, 7 +Vo

## ZY0JGCxxxxCD2-10W
designator U?
ZY0JGCxxxxCD2-10W
footprint ZY0JGCxxxxCD2-10W
pins: 1 AC(L), 2 AC(N), 3 FG, 4 -Vo1, 5 +Vo1, 6 -Vo2, 7 COM, 8 +Vo2

## ZY0JGCxxxxCDI1-5W
designator U?
ZY0JGCxxxxCDI1-5W
footprint ZY0JGCxxxxCDI1-5W
pins: 1 AC(L), 2 AC(N), 3 FG, 4 -Vo1, 5 +Vo1, 6 -Vo2, 7 COM, 8 +Vo2

## ZY0JGCxxxxD1-5W
designator U?
ZY0JGCxxxxD1-5W
footprint ZY0JGCxxxxD1-5W
pins: 1 AC(L), 2 AC(N), 3 FG, 4 -Vo1, 5 +Vo1, 6 -Vo2, 7 COM, 8 +Vo2

## ZY0JGCxxxxD2-15W
designator U?
ZY0JGCxxxxD2-15W
footprint ZY0JGCxxxxD2-15W
pins: 1 AC(L), 2 AC(N), 3 FG, 4 -Vo1, 5 +Vo1, 6 -Vo2, 7 COM, 8 +Vo2

## ZY0JGD05xxCD-10W
designator U?
footprint ZY0JGD05xxCD-10W
pins: 1 AC(L), 2 AC(N), 3 FG, 4 -Vo1, 5 +Vo1, 7 -Vo2, 8 +Vo2

## ZY0JGD05xxDx-20W
designator U?
footprint ZY0JGD05xxDx-20W
pins: 1 AC(L), 2 AC(N), 3 FG, 5 -Vo1, 6 +Vo1, 8 -Vo2, 9 +Vo2

## ZY0JGD0515DI2-15W
designator U?
footprint ZY0JGD0515DI2-15W
pins: 1 AC(L), 2 AC(N), 3 FG, 5 -Vo1, 6 +Vo1, 8 -Vo2, 9 +Vo2

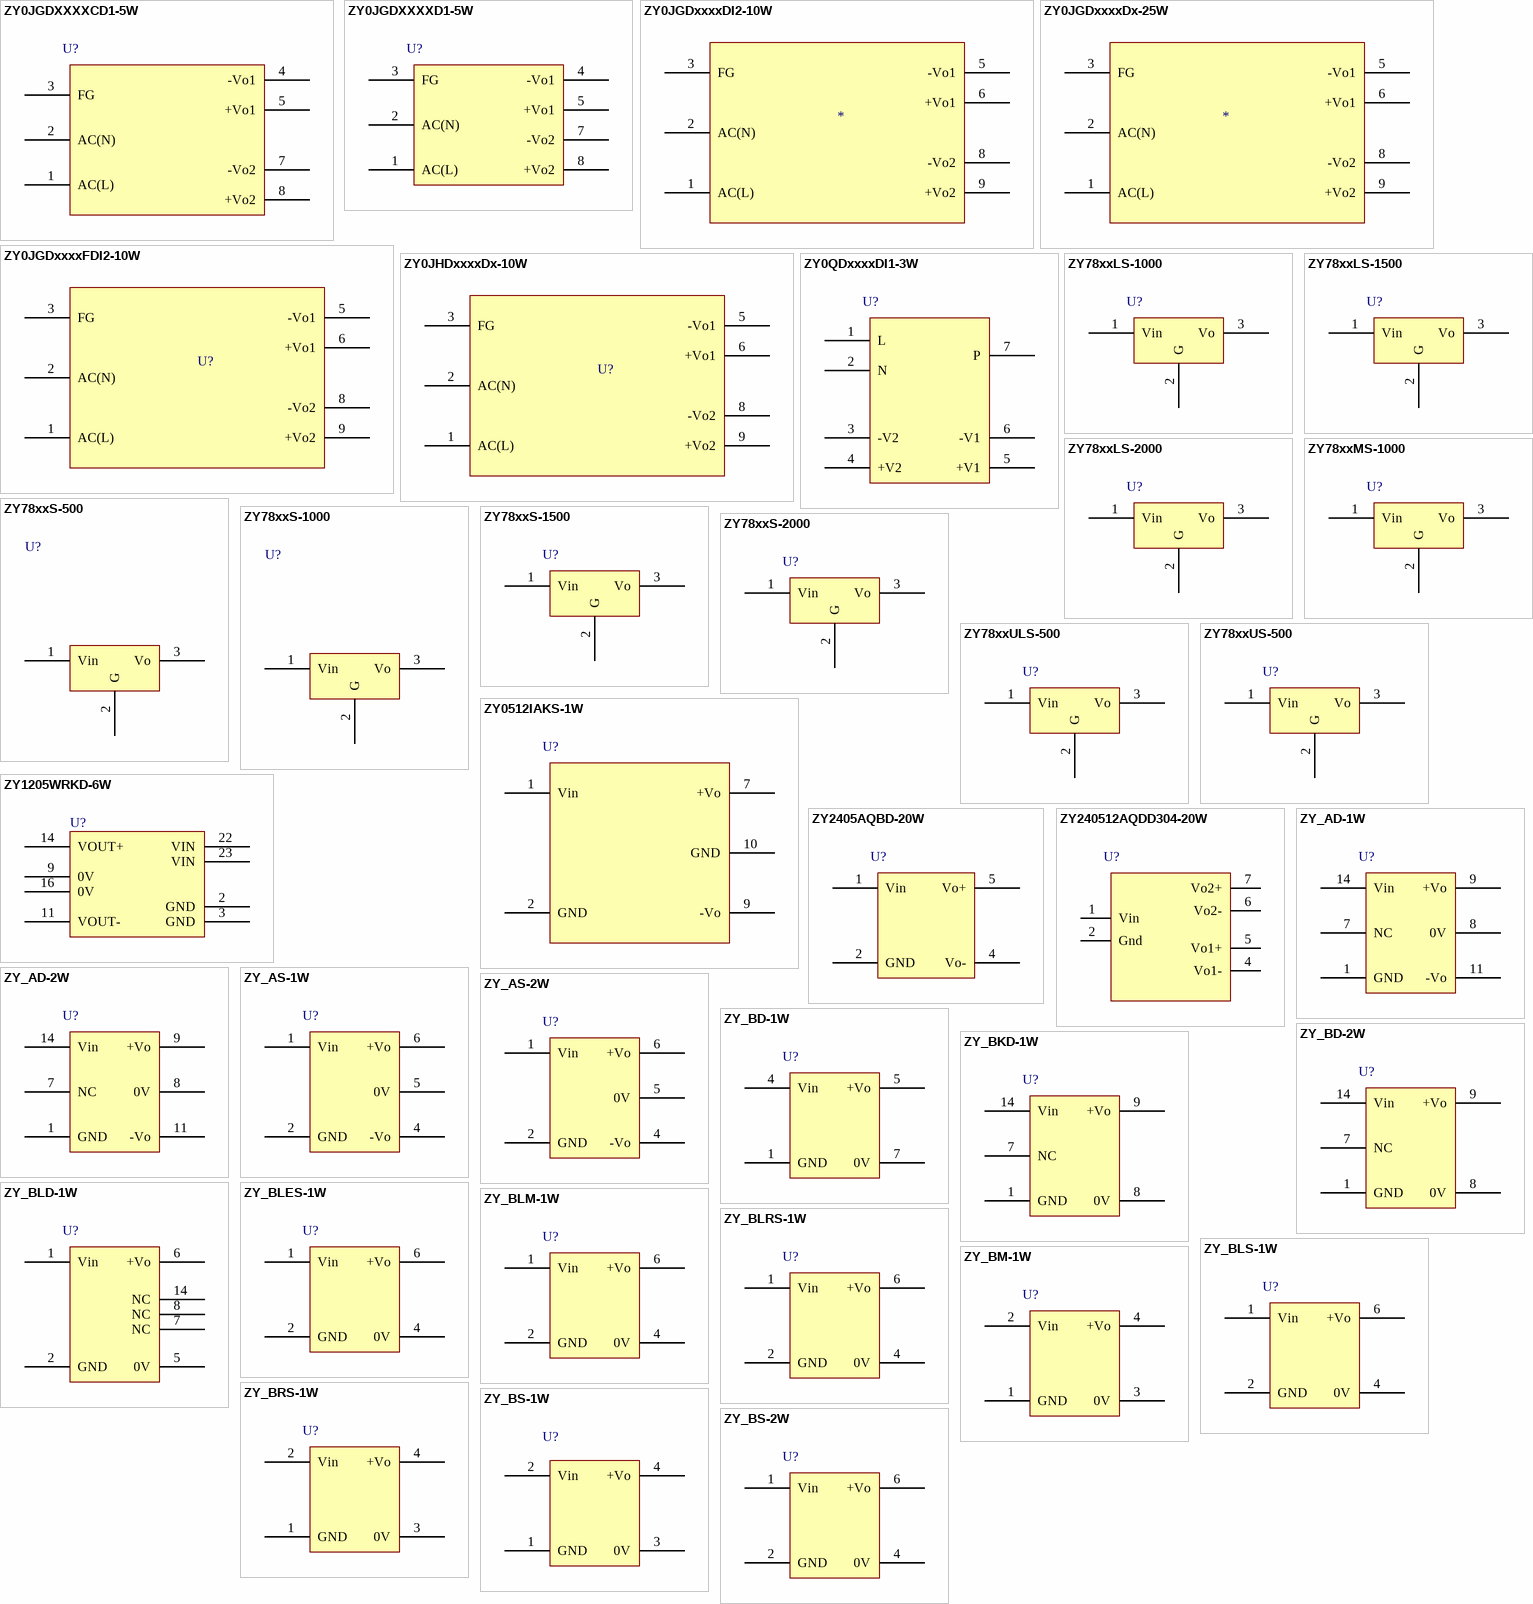
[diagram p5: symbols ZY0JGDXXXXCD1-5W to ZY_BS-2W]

## ZY0JGDXXXXCD1-5W
designator U?
footprint ZY0JGDXXXXCD1-5W (Footprint not found)
pins: 1 AC(L), 2 AC(N), 3 FG, 4 -Vo1, 5 +Vo1, 7 -Vo2, 8 +Vo2

## ZY0JGDXXXXD1-5W
designator U?
footprint ZY0JGDXXXXD1-5W
pins: 1 AC(L), 2 AC(N), 3 FG, 4 -Vo1, 5 +Vo1, 7 -Vo2, 8 +Vo2

## ZY0JGDxxxxDI2-10W
designator *
footprint ZY0JGDxxxxDI2-10W
pins: 1 AC(L), 2 AC(N), 3 FG, 5 -Vo1, 6 +Vo1, 8 -Vo2, 9 +Vo2

## ZY0JGDxxxxDx-25W
designator *
footprint ZY0JGDxxxxDx-25W
pins: 1 AC(L), 2 AC(N), 3 FG, 5 -Vo1, 6 +Vo1, 8 -Vo2, 9 +Vo2

## ZY0JGDxxxxFDI2-10W
designator U?
footprint ZY0JGDxxxxFDI2-10W
pins: 1 AC(L), 2 AC(N), 3 FG, 5 -Vo1, 6 +Vo1, 8 -Vo2, 9 +Vo2

## ZY0JHDxxxxDx-10W
designator U?
footprint ZY0JHDxxxxDx-10W
pins: 1 AC(L), 2 AC(N), 3 FG, 5 -Vo1, 6 +Vo1, 8 -Vo2, 9 +Vo2

## ZY0QDxxxxDI1-3W
designator U?
ZY0QDxxxxDI1-3W
footprint ZY0QDxxxxDI1-3W
pins: 1 L, 2 N, 3 -V2, 4 +V2, 5 +V1, 6 -V1, 7 P

## ZY78xxLS-1000
designator U?
footprint ZY78xxLS-1000
pins: 1 Vin, 2 G, 3 Vo

## ZY78xxLS-1500
designator U?
footprint ZY78xxLS-1500
pins: 1 Vin, 2 G, 3 Vo

## ZY78xxLS-2000
designator U?
footprint ZY78xxLS-2000
pins: 1 Vin, 2 G, 3 Vo

## ZY78xxMS-1000
designator U?
footprint ZY78xxMS-1000
pins: 1 Vin, 2 G, 3 Vo

## ZY78xxS-500
designator U?
footprint ZY78xxS-500
pins: 1 Vin, 2 G, 3 Vo

## ZY78xxS-1000
designator U?
footprint ZY78xxS-1000
pins: 1 Vin, 2 G, 3 Vo

## ZY78xxS-1500
designator U?
footprint ZY78xxS-1500
pins: 1 Vin, 2 G, 3 Vo

## ZY78xxS-2000
designator U?
footprint ZY78xxS-2000
pins: 1 Vin, 2 G, 3 Vo

## ZY78xxULS-500
designator U?
footprint ZY78xxULS-500 (Footprint not found)
pins: 1 Vin, 2 G, 3 Vo

## ZY78xxUS-500
designator U?
footprint ZY78xxUS-500
pins: 1 Vin, 2 G, 3 Vo

## ZY0512IAKS-1W
designator U?
pins: 1 Vin, 2 GND "Vin", 7 +Vo "Vin", 9 -Vo "Vin", 10 GND "Vin"

## ZY1205WRKD-6W
designator U?
pins: 2 GND (power), 3 GND (power), 9 0V (power), 11 VOUT- (power), 14 VOUT+ (power), 16 0V (power), 22 VIN (power), 23 VIN (power)

## ZY2405AQBD-20W
designator U?
footprint ZY2405AQBD-20W
pins: 1 Vin, 2 GND, 4 Vo-, 5 Vo+

## ZY240512AQDD304-20W
designator U?
footprint ZY240512AQDD304-20W
pins: 1 Vin, 2 Gnd, 4 Vo1-, 5 Vo1+, 6 Vo2-, 7 Vo2+

## ZY_AD-1W
designator U?
footprint ZY_AD-1W (定压输入隔离非稳压正、负输出)
pins: 1 GND, 7 NC, 8 0V, 9 +Vo, 11 -Vo, 14 Vin

## ZY_AD-2W
designator U?
footprint ZY_AD-2W
pins: 1 GND, 7 NC, 8 0V, 9 +Vo, 11 -Vo, 14 Vin

## ZY_AS-1W
designator U?
footprint ZY_AS-1W (定压输入隔离非稳压正、负双输出)
pins: 1 Vin, 2 GND, 4 -Vo, 5 0V, 6 +Vo

## ZY_AS-2W
designator U?
footprint ZY_AS-2W (定压输入隔离非稳压正、负双输出)
pins: 1 Vin, 2 GND, 4 -Vo, 5 0V, 6 +Vo

## ZY_BD-1W
designator U?
footprint ZY_BD-1W (Footprint not found)
pins: 1 GND, 4 Vin, 5 +Vo, 7 0V

## ZY_BD-2W
designator U?
footprint ZY_BD-2W
pins: 1 GND, 7 NC, 8 0V, 9 +Vo, 14 Vin

## ZY_BKD-1W
designator U?
footprint ZY_BKD-1W
pins: 1 GND, 7 NC, 8 0V, 9 +Vo, 14 Vin

## ZY_BLD-1W
designator U?
footprint ZY_BLD-1W (Footprint not found)
pins: 1 Vin, 2 GND, 5 0V, 6 +Vo, 7 NC, 8 NC, 14 NC

## ZY_BLES-1W
designator U?
footprint ZY_BLES-1W (Footprint not found)
pins: 1 Vin, 2 GND, 4 0V, 6 +Vo

## ZY_BLM-1W
designator U?
footprint ZY_BLM-1W
pins: 1 Vin, 2 GND, 4 0V, 6 +Vo

## ZY_BLRS-1W
designator U?
footprint ZY_BLRS-1W (Footprint not found)
pins: 1 Vin, 2 GND, 4 0V, 6 +Vo

## ZY_BLS-1W
designator U?
footprint ZY_BLS-1W (定压输入隔离非稳压单输出)
pins: 1 Vin, 2 GND, 4 0V, 6 +Vo

## ZY_BM-1W
designator U?
footprint ZY_BM-1W (Footprint not found)
pins: 1 GND, 2 Vin, 3 0V, 4 +Vo

## ZY_BRS-1W
designator U?
footprint ZY_BRS-1W
pins: 1 GND, 2 Vin, 3 0V, 4 +Vo

## ZY_BS-1W
designator U?
footprint ZY_BS-1W (Footprint not found)
pins: 1 GND, 2 Vin, 3 0V, 4 +Vo

## ZY_BS-2W
designator U?
footprint ZY_BS-2W (定压输入隔离非稳压单输出)
pins: 1 Vin, 2 GND, 4 0V, 6 +Vo

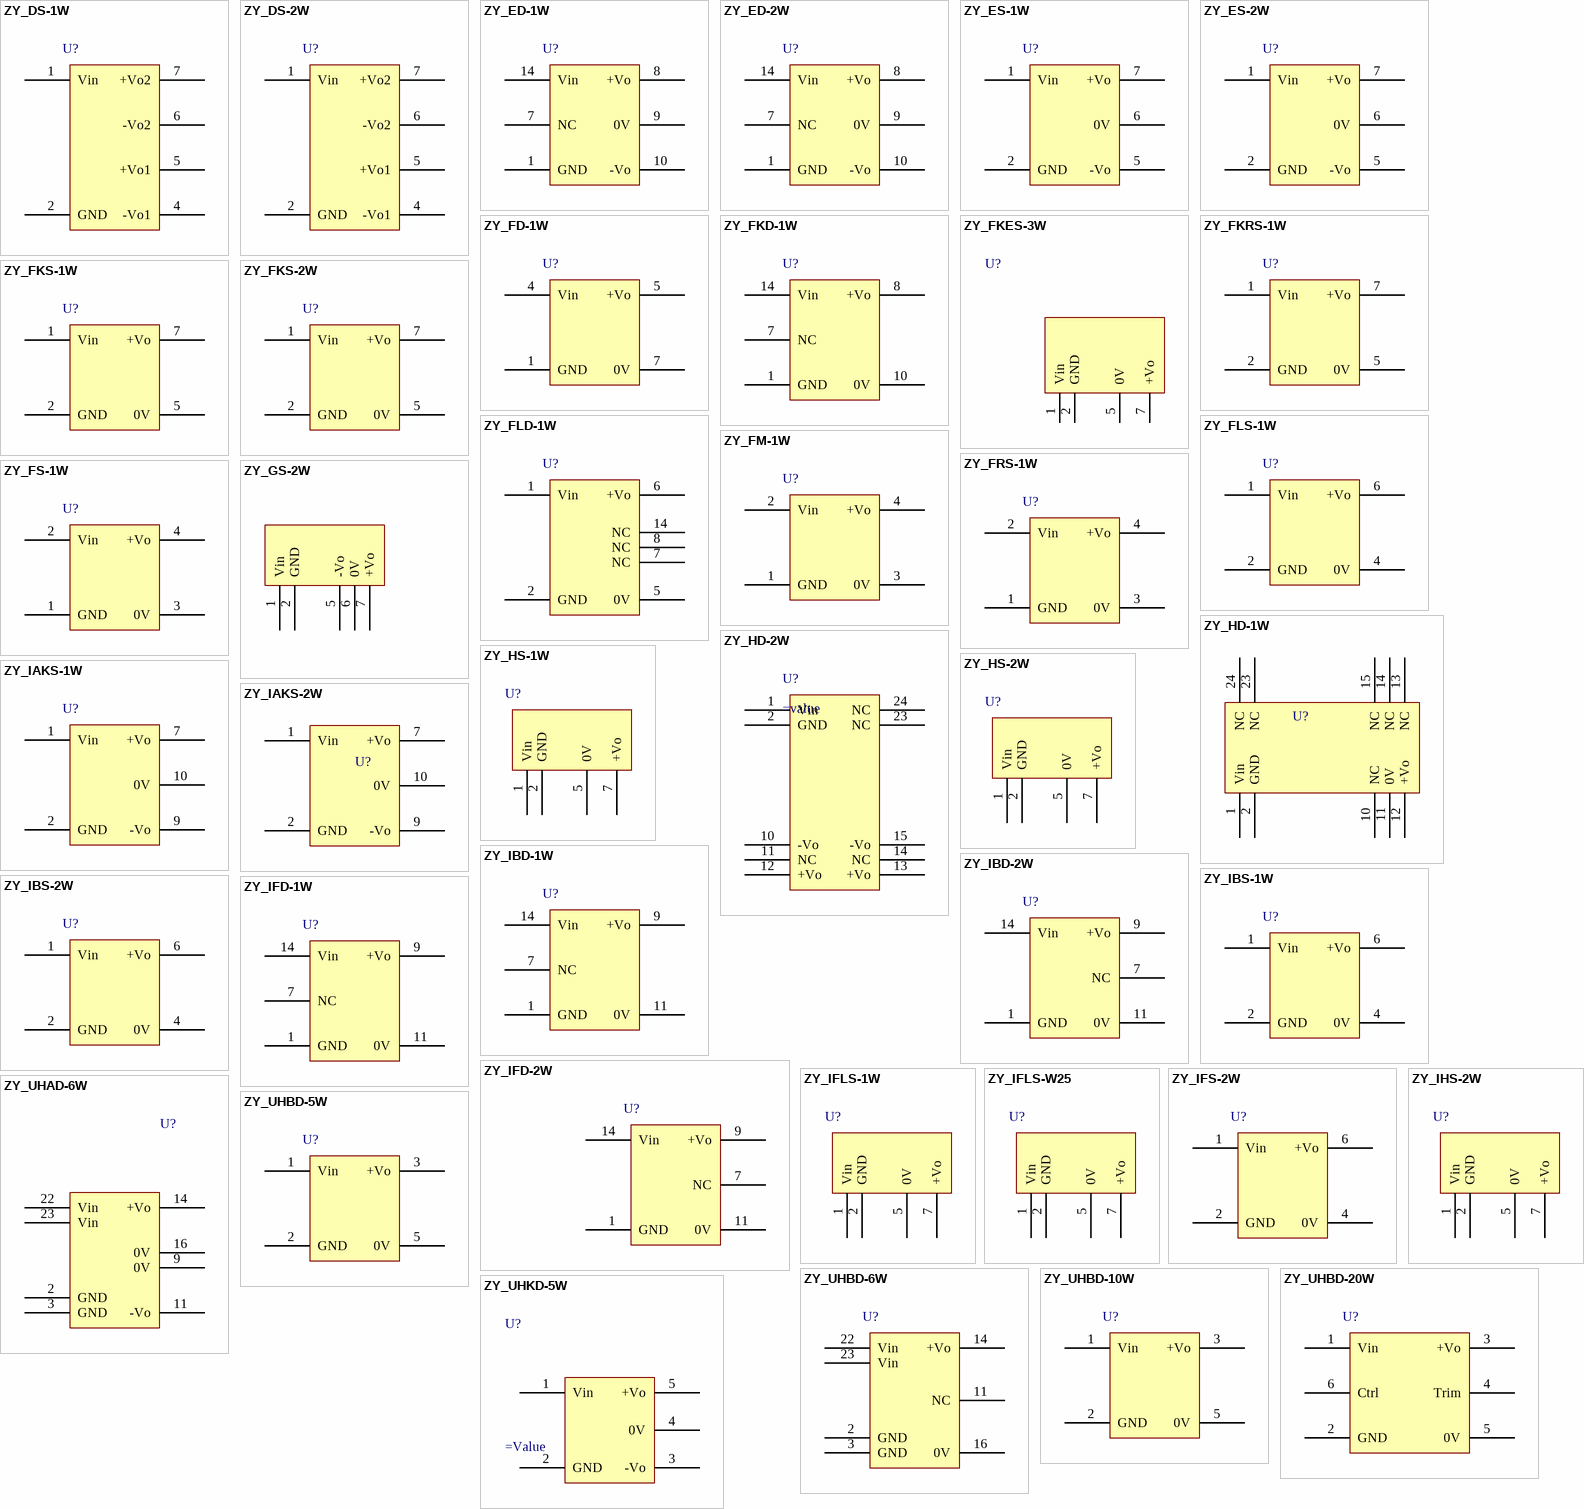
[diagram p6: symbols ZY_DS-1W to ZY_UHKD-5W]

## ZY_DS-1W
designator U?
footprint ZY_DS-1W
pins: 1 Vin, 2 GND, 4 -Vo1, 5 +Vo1, 6 -Vo2, 7 +Vo2

## ZY_DS-2W
designator U?
footprint ZY_DS-2W (Footprint not found)
pins: 1 Vin, 2 GND, 4 -Vo1, 5 +Vo1, 6 -Vo2, 7 +Vo2

## ZY_ED-1W
designator U?
footprint ZY_ED-1W (定压输入隔离非稳压正、负输出)
pins: 1 GND, 7 NC, 8 +Vo, 9 0V, 10 -Vo, 14 Vin

## ZY_ED-2W
designator U?
footprint ZY_ED-2W (Footprint not found)
pins: 1 GND, 7 NC, 8 +Vo, 9 0V, 10 -Vo, 14 Vin

## ZY_ES-1W
designator U?
footprint ZY_ES-1W (定压输入隔离非稳压正、负输出)
pins: 1 Vin, 2 GND, 5 -Vo, 6 0V, 7 +Vo

## ZY_ES-2W
designator U?
footprint ZY_ES-2W (定压输入隔离非稳压双输出)
pins: 1 Vin, 2 GND, 5 -Vo, 6 0V, 7 +Vo

## ZY_FD-1W
designator U?
footprint ZY_FD-1W (Footprint not found)
pins: 1 GND, 4 Vin, 5 +Vo, 7 0V

## ZY_FKD-1W
designator U?
footprint ZY_FKD-1W
pins: 1 GND, 7 NC, 8 +Vo, 10 0V, 14 Vin

## ZY_FKES-3W
designator U?
footprint ZY_FKES-3W
pins: 1 Vin, 2 GND, 5 0V, 7 +Vo

## ZY_FKRS-1W
designator U?
footprint ZY_FKRS-1W
pins: 1 Vin, 2 GND, 5 0V, 7 +Vo

## ZY_FKS-1W
designator U?
footprint ZY_FKS-1W
pins: 1 Vin, 2 GND, 5 0V, 7 +Vo

## ZY_FKS-2W
designator U?
footprint ZY_FKS-2W
pins: 1 Vin, 2 GND, 5 0V, 7 +Vo

## ZY_FLD-1W
designator U?
footprint ZY_FLD-1W (定压输入隔离非稳压单输出)
pins: 1 Vin, 2 GND, 5 0V, 6 +Vo, 7 NC, 8 NC, 14 NC

## ZY_FLS-1W
designator U?
footprint ZY_FLS-1W
pins: 1 Vin, 2 GND, 4 0V, 6 +Vo

## ZY_FM-1W
designator U?
footprint ZY_FM-1W (Footprint not found)
pins: 1 GND, 2 Vin, 3 0V, 4 +Vo

## ZY_FRS-1W
designator U?
footprint ZY_FRS-1W
pins: 1 GND, 2 Vin, 3 0V, 4 +Vo

## ZY_FS-1W
designator U?
footprint ZY_FS-1W (定压输入隔离非稳压单输出)
pins: 1 GND, 2 Vin, 3 0V, 4 +Vo

## ZY_GS-2W
designator U?
footprint ZY_GS-2W
pins: 1 Vin, 2 GND, 5 -Vo, 6 0V, 7 +Vo

## ZY_HD-1W
designator U?
footprint ZY_HD-1W
pins: 1 Vin, 2 GND, 10 NC, 11 0V, 12 +Vo, 13 NC, 14 NC, 15 NC, 23 NC, 24 NC

## ZY_HD-2W
designator U?
footprint ZY_HD-2W
pins: 1 Vin, 2 GND, 10 -Vo, 11 NC, 12 +Vo, 13 +Vo, 14 NC, 15 -Vo, 23 NC, 24 NC

## ZY_HS-1W
designator U?
footprint ZY_HS-1W
pins: 1 Vin, 2 GND, 5 0V, 7 +Vo

## ZY_HS-2W
designator U?
footprint ZY_HS-2W
pins: 1 Vin, 2 GND, 5 0V, 7 +Vo

## ZY_IAKS-1W
designator U?
footprint ZY_IAKS-1W (定压输入隔离稳压双输出)
pins: 1 Vin, 2 GND, 7 +Vo, 9 -Vo, 10 0V

## ZY_IAKS-2W
designator U?
footprint ZY_IAKS-2W
pins: 1 Vin, 2 GND, 7 +Vo, 9 -Vo, 10 0V

## ZY_IBD-1W
designator U?
footprint ZY_IBD-1W
pins: 1 GND, 7 NC, 9 +Vo, 11 0V, 14 Vin

## ZY_IBD-2W
designator U?
footprint ZY_IBD-2W
pins: 1 GND, 7 NC, 9 +Vo, 11 0V, 14 Vin

## ZY_IBS-1W
designator U?
footprint ZY_IBS-1W (定压输入隔离稳压单输出)
pins: 1 Vin, 2 GND, 4 0V, 6 +Vo

## ZY_IBS-2W
designator U?
footprint ZY_IBS-2W
pins: 1 Vin, 2 GND, 4 0V, 6 +Vo

## ZY_IFD-1W
designator U?
footprint ZY_IFD-1W
pins: 1 GND, 7 NC, 9 +Vo, 11 0V, 14 Vin

## ZY_IFD-2W
designator U?
footprint ZY_IFD-2W
pins: 1 GND, 7 NC, 9 +Vo, 11 0V, 14 Vin

## ZY_IFLS-1W
designator U?
footprint ZY_IFLS-1W
pins: 1 Vin, 2 GND, 5 0V, 7 +Vo

## ZY_IFLS-W25
designator U?
footprint ZY_IFLS-W25
pins: 1 Vin, 2 GND, 5 0V, 7 +Vo

## ZY_IFS-2W
designator U?
footprint ZY_IFS-2W
pins: 1 Vin, 2 GND, 4 0V, 6 +Vo

## ZY_IHS-2W
designator U?
footprint ZY_IHS-2W
pins: 1 Vin, 2 GND, 5 0V, 7 +Vo

## ZY_UHAD-6W
designator U?
footprint ZY_UHAD-6W (Footprint not found)
pins: 2 GND, 3 GND, 9 0V, 11 -Vo, 14 +Vo, 16 0V, 22 Vin, 23 Vin

## ZY_UHBD-5W
designator U?
footprint ZY_UHBD-5W
pins: 1 Vin, 2 GND, 3 +Vo, 5 0V

## ZY_UHBD-6W
designator U?
footprint ZY_UHBD-6W
pins: 2 GND, 3 GND, 11 NC, 14 +Vo, 16 0V, 22 Vin, 23 Vin

## ZY_UHBD-10W
designator U?
footprint ZY_UHBD-10W (Footprint not found)
pins: 1 Vin, 2 GND, 3 +Vo, 5 0V

## ZY_UHBD-20W
designator U?
footprint ZY_UHBD-20W
pins: 1 Vin, 2 GND, 3 +Vo, 4 Trim, 5 0V, 6 Ctrl

## ZY_UHKD-5W
designator U?
footprint ZY_UHKD-5W
pins: 1 Vin, 2 GND, 3 -Vo, 4 0V, 5 +Vo

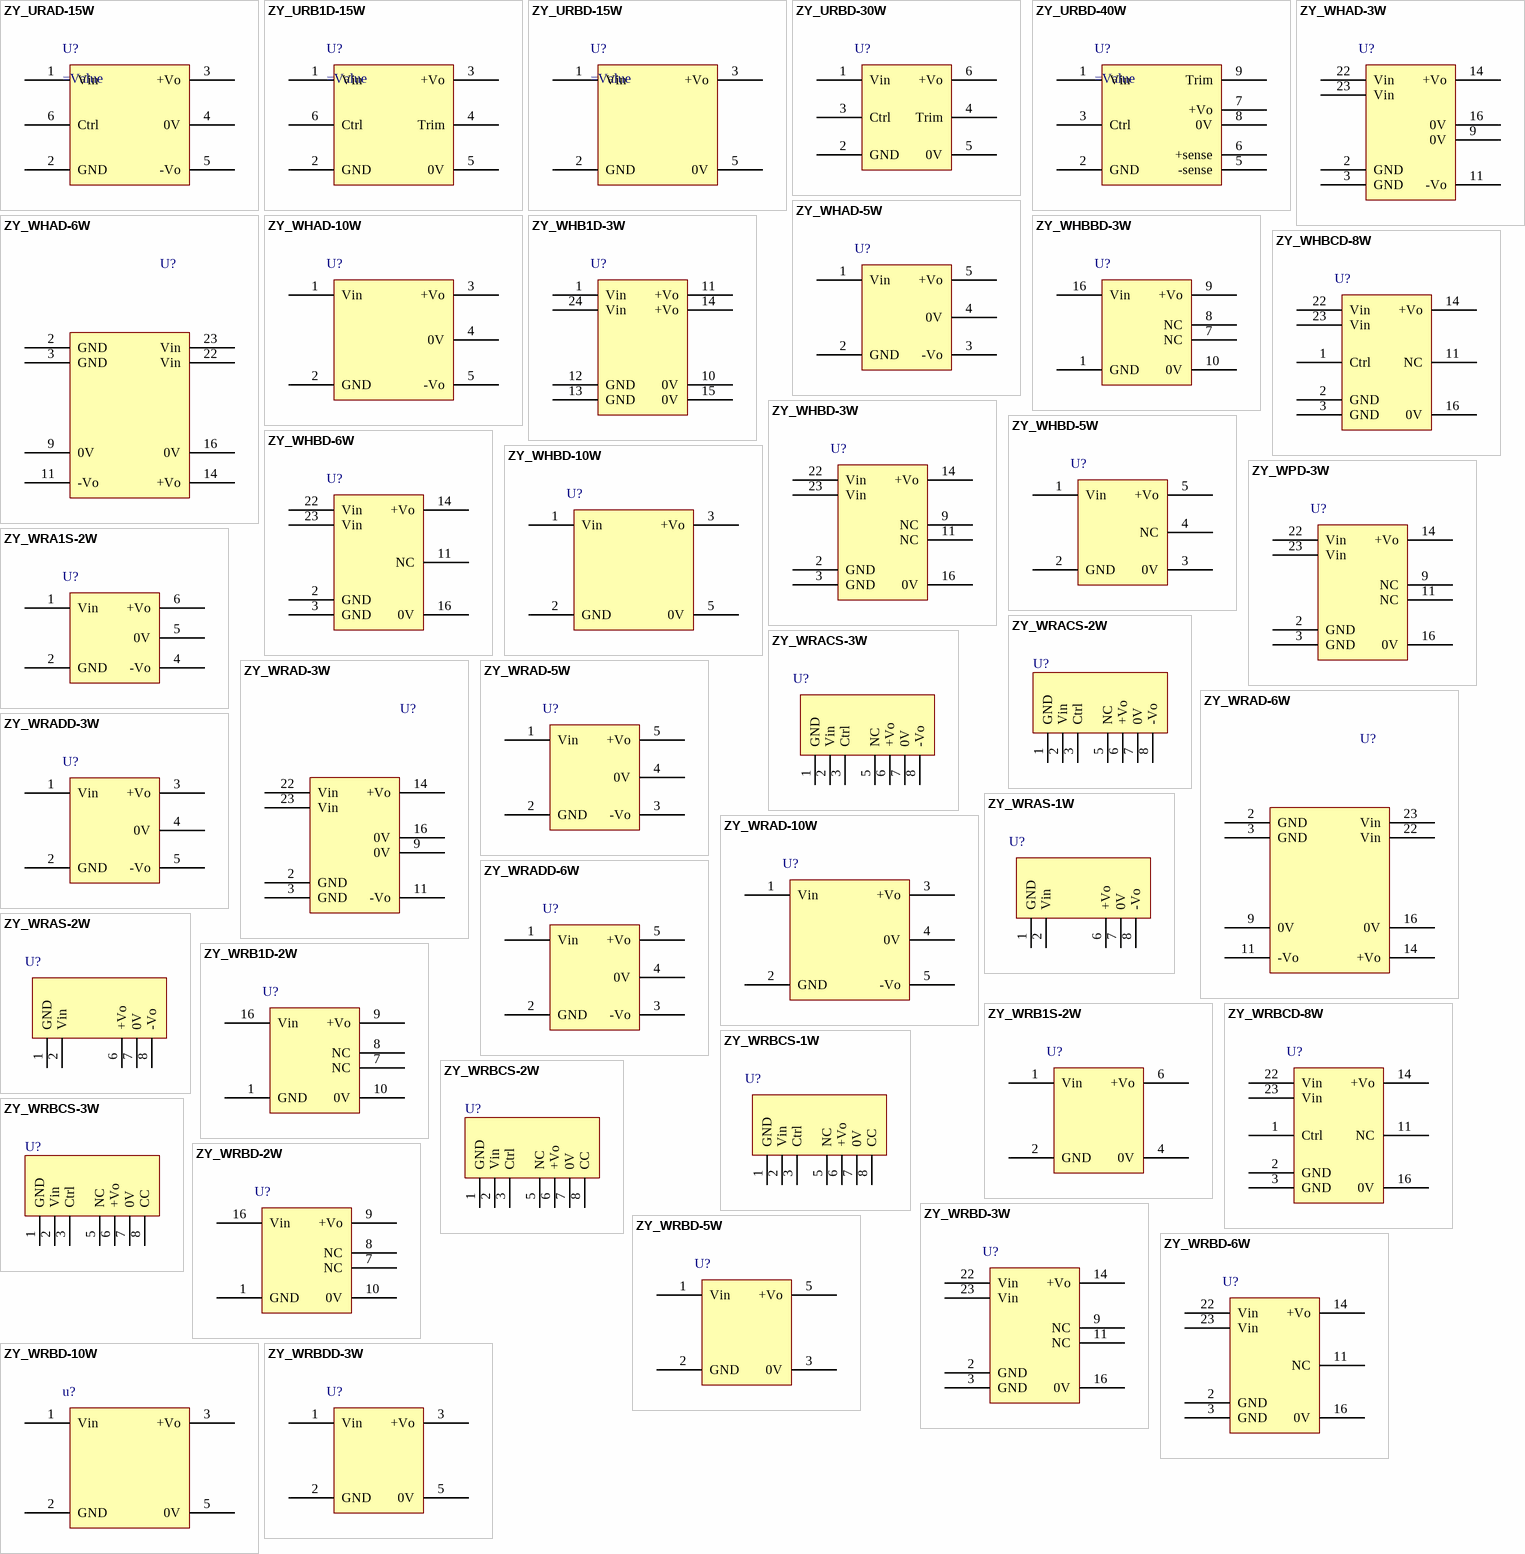
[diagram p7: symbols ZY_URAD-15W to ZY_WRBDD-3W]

## ZY_URAD-15W
designator U?
footprint ZY_URAD-15W
pins: 1 Vin, 2 GND, 3 +Vo, 4 0V, 5 -Vo, 6 Ctrl

## ZY_URB1D-15W
designator U?
footprint ZY_URB1D-15W
pins: 1 Vin, 2 GND, 3 +Vo, 4 Trim, 5 0V, 6 Ctrl

## ZY_URBD-15W
designator U?
footprint ZY_URBD-15W
pins: 1 Vin, 2 GND, 3 +Vo, 5 0V

## ZY_URBD-30W
designator U?
footprint ZY_URBD-30W
pins: 1 Vin, 2 GND, 3 Ctrl, 4 Trim, 5 0V, 6 +Vo

## ZY_URBD-40W
designator U?
footprint ZY_URBD-40W
pins: 1 Vin, 2 GND, 3 Ctrl, 5 -sense, 6 +sense, 7 +Vo, 8 0V, 9 Trim

## ZY_WHAD-3W
designator U?
footprint ZY_WHAD-3W (宽压输入隔离稳压双输出电源模块)
pins: 2 GND, 3 GND, 9 0V, 11 -Vo, 14 +Vo, 16 0V, 22 Vin, 23 Vin

## ZY_WHAD-5W
designator U?
footprint ZY_WHAD-5W
pins: 1 Vin, 2 GND, 3 -Vo, 4 0V, 5 +Vo

## ZY_WHAD-6W
designator U?
footprint ZY_WHAD-6W (Footprint not found)
pins: 2 GND, 3 GND, 9 0V, 11 -Vo, 14 +Vo, 16 0V, 22 Vin, 23 Vin

## ZY_WHAD-10W
designator U?
footprint ZY_WHAD-10W
pins: 1 Vin, 2 GND, 3 +Vo, 4 0V, 5 -Vo

## ZY_WHB1D-3W
designator U?
footprint ZY_WHB1D-3W
pins: 1 Vin, 10 0V, 11 +Vo, 12 GND, 13 GND, 14 +Vo, 15 0V, 24 Vin

## ZY_WHBBD-3W
designator U?
footprint ZY_WHBBD-3W (Footprint not found)
pins: 1 GND, 7 NC, 8 NC, 9 +Vo, 10 0V, 16 Vin

## ZY_WHBCD-8W
designator U?
footprint ZY_WHBCD-8W
pins: 1 Ctrl, 2 GND, 3 GND, 11 NC, 14 +Vo, 16 0V, 22 Vin, 23 Vin

## ZY_WHBD-3W
designator U?
footprint ZY_WHBD-3W (宽压输入隔离稳压单输出电源模块)
pins: 2 GND, 3 GND, 9 NC, 11 NC, 14 +Vo, 16 0V, 22 Vin, 23 Vin

## ZY_WHBD-5W
designator U?
footprint ZY_WHBD-5W
pins: 1 Vin, 2 GND, 3 0V, 4 NC, 5 +Vo

## ZY_WHBD-6W
designator U?
footprint ZY_WHBD-6W (Footprint not found)
pins: 2 GND, 3 GND, 11 NC, 14 +Vo, 16 0V, 22 Vin, 23 Vin

## ZY_WHBD-10W
designator U?
footprint ZY_WHBD-10W
pins: 1 Vin, 2 GND, 3 +Vo, 5 0V

## ZY_WPD-3W
designator U?
footprint ZY_WPD-3W (宽压输入非隔离稳压单输出)
pins: 2 GND, 3 GND, 9 NC, 11 NC, 14 +Vo, 16 0V, 22 Vin, 23 Vin

## ZY_WRA1S-2W
designator U?
footprint ZY_WRA1S-2W
pins: 1 Vin, 2 GND, 4 -Vo, 5 0V, 6 +Vo

## ZY_WRACS-2W
designator U?
footprint ZY_WRACS-2W
pins: 1 GND, 2 Vin, 3 Ctrl, 5 NC, 6 +Vo, 7 0V, 8 -Vo

## ZY_WRACS-3W
designator U?
footprint ZY_WRACS-3W
pins: 1 GND, 2 Vin, 3 Ctrl, 5 NC, 6 +Vo, 7 0V, 8 -Vo

## ZY_WRAD-3W
designator U?
footprint ZY_WRAD-3W
pins: 2 GND, 3 GND, 9 0V, 11 -Vo, 14 +Vo, 16 0V, 22 Vin, 23 Vin

## ZY_WRAD-5W
designator U?
footprint ZY_WRAD-5W
pins: 1 Vin, 2 GND, 3 -Vo, 4 0V, 5 +Vo

## ZY_WRAD-6W
designator U?
footprint ZY_WRAD-6W
pins: 2 GND, 3 GND, 9 0V, 11 -Vo, 14 +Vo, 16 0V, 22 Vin, 23 Vin

## ZY_WRAD-10W
designator U?
footprint ZY_WRAD-10W
pins: 1 Vin, 2 GND, 3 +Vo, 4 0V, 5 -Vo

## ZY_WRADD-3W
designator U?
footprint ZY_WRADD-3W
pins: 1 Vin, 2 GND, 3 +Vo, 4 0V, 5 -Vo

## ZY_WRADD-6W
designator U?
footprint ZY_WRADD-6W
pins: 1 Vin, 2 GND, 3 -Vo, 4 0V, 5 +Vo

## ZY_WRAS-1W
designator U?
footprint ZY_WRAS-1W
pins: 1 GND, 2 Vin, 6 +Vo, 7 0V, 8 -Vo

## ZY_WRAS-2W
designator U?
footprint ZY_WRAS-2W
pins: 1 GND, 2 Vin, 6 +Vo, 7 0V, 8 -Vo

## ZY_WRB1D-2W
designator U?
footprint ZY_WRB1D-2W (Footprint not found)
pins: 1 GND, 7 NC, 8 NC, 9 +Vo, 10 0V, 16 Vin

## ZY_WRB1S-2W
designator U?
footprint ZY_WRB1S-2W (Footprint not found)
pins: 1 Vin, 2 GND, 4 0V, 6 +Vo

## ZY_WRBCD-8W
designator U?
footprint ZY_WRBCD-8W
pins: 1 Ctrl, 2 GND, 3 GND, 11 NC, 14 +Vo, 16 0V, 22 Vin, 23 Vin

## ZY_WRBCS-1W
designator U?
footprint ZY_WRBCS-1W
pins: 1 GND, 2 Vin, 3 Ctrl, 5 NC, 6 +Vo, 7 0V, 8 CC

## ZY_WRBCS-2W
designator U?
footprint ZY_WRBCS-2W
pins: 1 GND, 2 Vin, 3 Ctrl, 5 NC, 6 +Vo, 7 0V, 8 CC

## ZY_WRBCS-3W
designator U?
footprint ZY_WRBCS-3W (Footprint not found)
pins: 1 GND, 2 Vin, 3 Ctrl, 5 NC, 6 +Vo, 7 0V, 8 CC

## ZY_WRBD-2W
designator U?
footprint ZY_WRBD-2W
pins: 1 GND, 7 NC, 8 NC, 9 +Vo, 10 0V, 16 Vin

## ZY_WRBD-3W
designator U?
footprint ZY_WRBD-3W (宽压输入隔离稳压单输出电源模块)
pins: 2 GND, 3 GND, 9 NC, 11 NC, 14 +Vo, 16 0V, 22 Vin, 23 Vin

## ZY_WRBD-5W
designator U?
footprint ZY_WRBD-5W
pins: 1 Vin, 2 GND, 3 0V, 5 +Vo

## ZY_WRBD-6W
designator U?
footprint ZY_WRBD-6W
pins: 2 GND, 3 GND, 11 NC, 14 +Vo, 16 0V, 22 Vin, 23 Vin

## ZY_WRBD-10W
designator u?
footprint ZY_WRBD-10W
pins: 1 Vin, 2 GND, 3 +Vo, 5 0V

## ZY_WRBDD-3W
designator U?
footprint ZY_WRBDD-3W
pins: 1 Vin, 2 GND, 3 +Vo, 5 0V

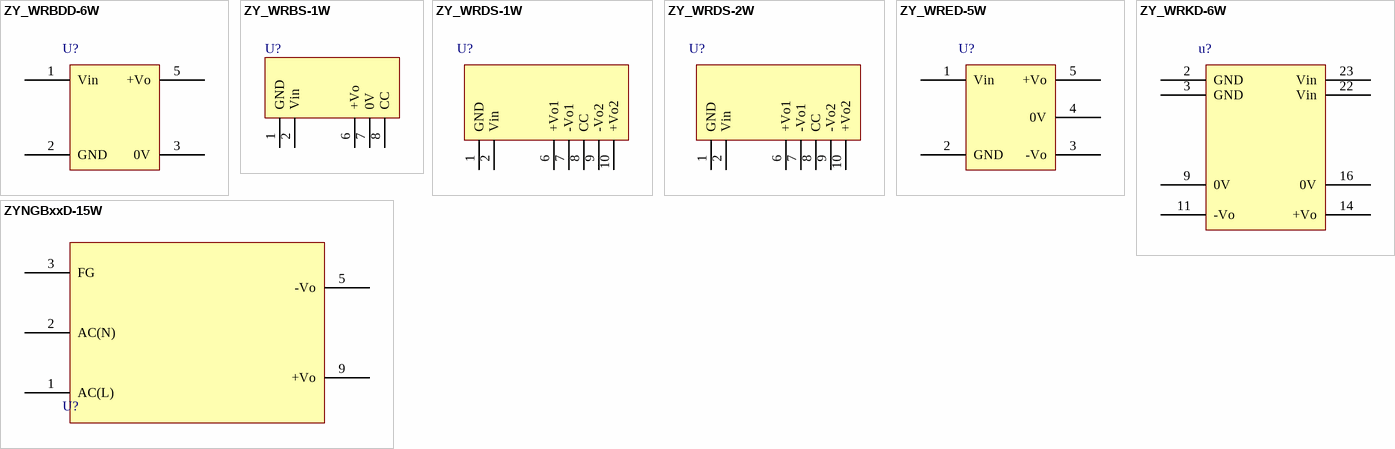
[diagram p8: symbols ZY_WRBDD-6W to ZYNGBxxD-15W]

## ZY_WRBDD-6W
designator U?
footprint ZY_WRBDD-6W
pins: 1 Vin, 2 GND, 3 0V, 5 +Vo

## ZY_WRBS-1W
designator U?
footprint ZY_WRBS-1W
pins: 1 GND, 2 Vin, 6 +Vo, 7 0V, 8 CC

## ZY_WRDS-1W
designator U?
footprint ZY_WRDS-1W
pins: 1 GND, 2 Vin, 6 +Vo1, 7 -Vo1, 8 CC, 9 -Vo2, 10 +Vo2

## ZY_WRDS-2W
designator U?
footprint ZY_WRDS-2W
pins: 1 GND, 2 Vin, 6 +Vo1, 7 -Vo1, 8 CC, 9 -Vo2, 10 +Vo2

## ZY_WRED-5W
designator U?
footprint ZY_WRED-5W
pins: 1 Vin, 2 GND, 3 -Vo, 4 0V, 5 +Vo

## ZY_WRKD-6W
designator u?
footprint ZY_WRKD-6W
pins: 2 GND, 3 GND, 9 0V, 11 -Vo, 14 +Vo, 16 0V, 22 Vin, 23 Vin

## ZYNGBxxD-15W
designator U?
footprint ZYNGBxxD-15W (120426 修改 by kong)
pins: 1 AC(L), 2 AC(N), 3 FG, 5 -Vo, 9 +Vo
